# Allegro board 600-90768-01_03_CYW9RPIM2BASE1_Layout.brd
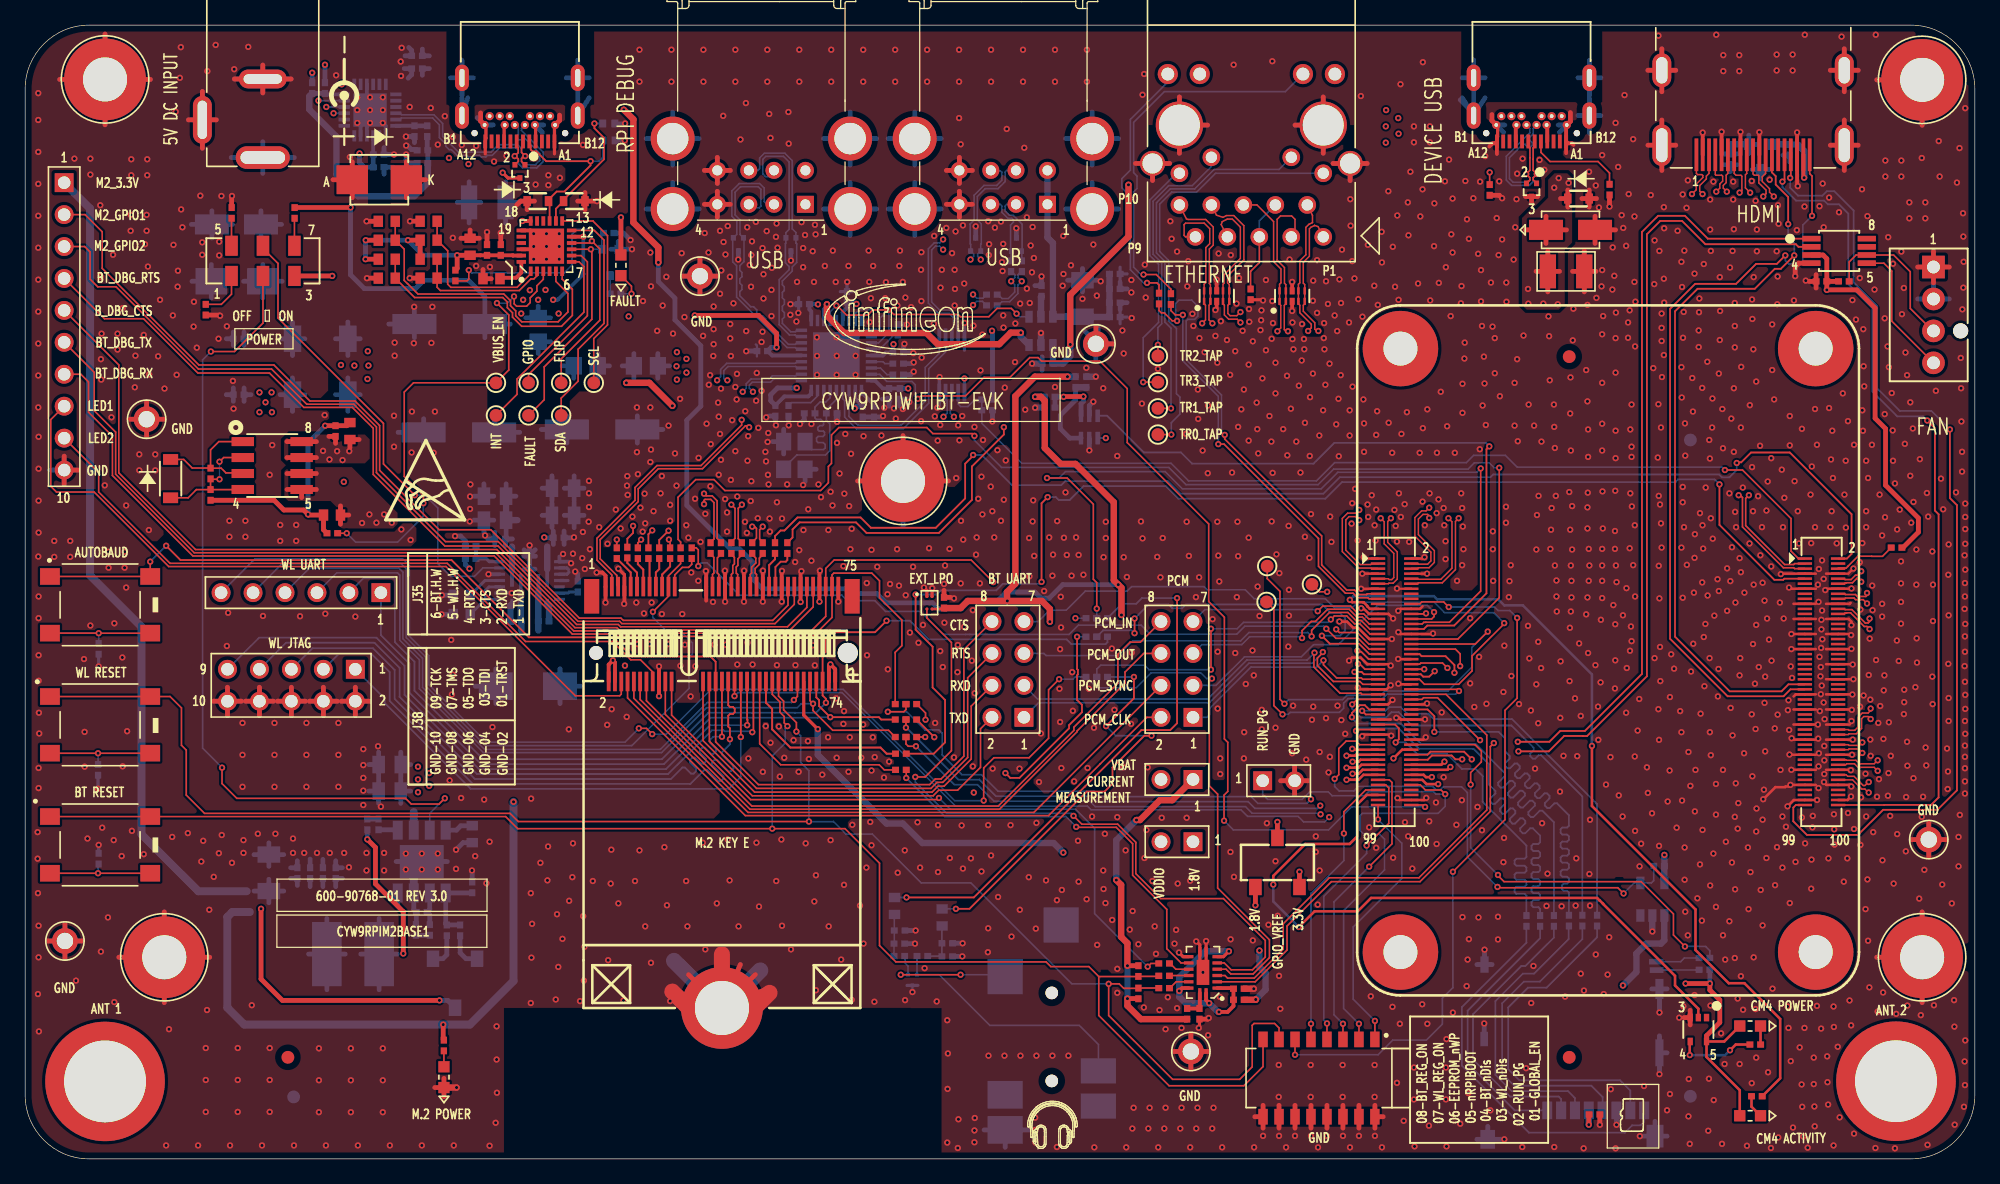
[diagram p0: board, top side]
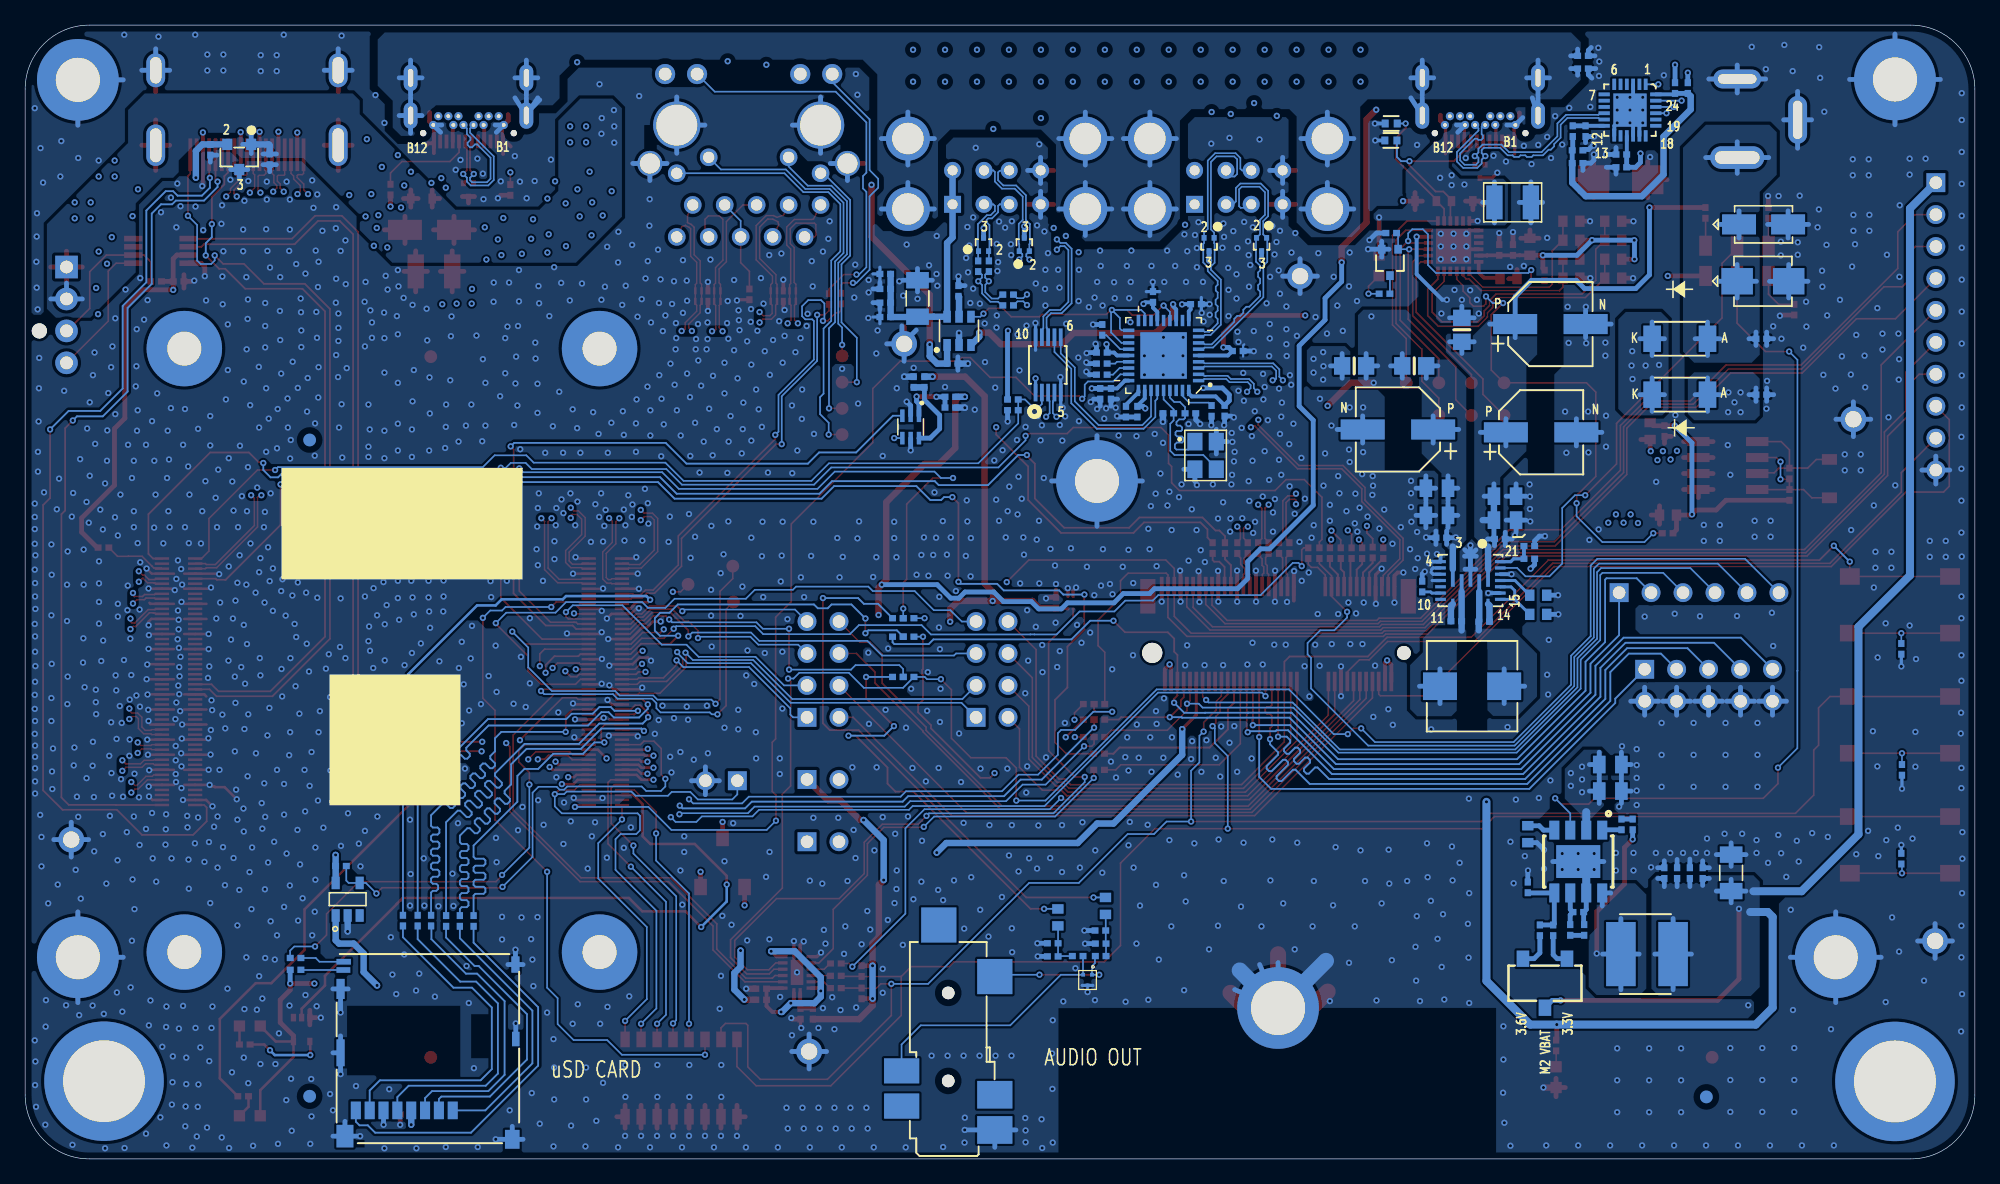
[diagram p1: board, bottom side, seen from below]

Outline 154.94 x 90.17 mm; copper layers: TOP, L02_GND, L03_PWR, L04, L05, BOTTOM. Coordinates in mm from the lower left corner of the outline.
Outline path: 0,85.09 0,5.08 arc(1.49,1.49) 5.08,0 149.86,0 arc(153.45,1.49) 154.94,5.08 154.94,85.09 arc(153.45,88.68) 149.86,90.17 5.08,90.17 arc(1.49,88.68) 0,85.09

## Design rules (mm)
constraint set DEFAULT: min track width 0.127
net group DIFFPAIR0: nets BT_USB_DN BT_USB_DP
net group DP3: nets USBRPI_DM USBRPI_DP
net group HD1: nets HD1_N HD1_P
net group HD1_M2: nets HD1_M2_N HD1_M2_P
net group HD1_PORT: nets HD1_PORT_N HD1_PORT_P
net group HD2: nets HD2_N HD2_P
net group HD3: nets HD3_N HD3_P
net group HD4: nets HD4_N HD4_P
net group PCIE_CLK_N: nets N17494909 PCIE_CLK_N
net group PCIE_CLK_P: nets N17494904 PCIE_CLK_P
net group PCIE_RX_N: nets N17494929 PCIE_RX_N
net group PCIE_RX_P: nets N17494926 PCIE_RX_P
net group PCIE_TX_N: nets N17494923 PCIE_TX_N
net group PCIE_TX_P: nets N17494920 PCIE_TX_P
net group SD_CLK: nets N17568415 SD_CLK
net group SD_CMD: nets N17568375 SD_CMD
net group SD_DAT0: nets N17569067 SD_DAT0
net group SD_DAT1: nets N17569095 SD_DAT1
net group SD_DAT2: nets N17568318 SD_DAT2
net group SD_DAT3: nets N17568347 SD_DAT3
net group TRD0: nets TRD0_N TRD0_P
net group TRD1: nets TRD1_N TRD1_P
net group TRD2: nets TRD2_N TRD2_P
net group TRD3: nets TRD3_N TRD3_P
net group USB2: nets USB2_N USB2_P
net group HDMI: nets HDMI0_CK_N HDMI0_CK_P HDMI0_D0_N HDMI0_D0_P HDMI0_D1_N HDMI0_D1_P HDMI0_D2_N HDMI0_D2_P
net group JTAG: nets WL_JTAG_TCK WL_JTAG_TDI WL_JTAG_TDO WL_JTAG_TMS
net group PWR: nets 1.8V 3.3V HDMI_5V M2_3.3V V3P3 VBUS VCCD VCCD_17758174 VDDD VDDIO
net group PWR_PH: nets 5V_IN GND_EARTH GPIO_VREF SD_PWR
net group SE_50E: nets GPIO8 GPIO9 HDMI0_SCL HDMI0_SDA PWM0_0 PWM0_1 PWR1 RXD SCL0 SDA0 TXD WL_JTAG_TRST WL_UART_RXD WL_UART_TXD
nets with their own width: min track width 0.381; nets GND

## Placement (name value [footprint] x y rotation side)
C1  10uF  [CAPC1005_IS0402Q]  81.24 63.25 180 bottom
C2  100uF  [CAPC3216_IS1206N]  84.03 68.43 90 bottom
C3  10uF  [CAPC1005_IS0402Q]  86.59 70.38 0 bottom
C4  10uF  [CAPC1005_IS0402Q]  86.59 69.19 0 bottom
C5  10uF  [CAPC1005_IS0402Q]  86.59 68.1 0 bottom
C6  10uF  [CAPC1005_IS0402Q]  86.59 66.95 0 bottom
C7  27pF  [CAPC1005_IS0402Q]  62.34 59.3 180 bottom
C8  27pF  [CAPC1005_IS0402Q]  64.1 59.3 0 bottom
C9  10uF  [CAPC1005_IS0402Q]  69.51 60.85 270 bottom
C10  10uF  [CAPC1005_IS0402Q]  68.65 60.85 270 bottom
C11  0.1uF  [CAPC1005_IS0402Q]  61.9 67.98 180 bottom
C12  0.1uF  [CAPC1005_IS0402Q]  65.31 68.55 90 bottom
C13  0.1uF  [CAPC1005_IS0402Q]  69.38 64.13 0 bottom
C14  0.1uF  [CAPC1005_IS0402Q]  66.55 59.43 270 bottom
C15  0.1uF  [CAPC1005_IS0402Q]  58.58 64.25 180 bottom
C16  0.1uF  [CAPC1005_IS0402Q]  59.62 59.5 270 bottom
C17  0.1uF  [CAPC1005_IS0402Q]  135.51 79.5 270 bottom
C18  0.1uF  [CAPC1005_IS0402Q]  140.22 80.26 270 bottom
C19  0.1uF  [CAPC1005_IS0402Q]  142.75 69.79 180 top
C20  10uF  [CAPC1005_IS0402Q]  124.71 3.53 0 top
C21  0.1uF  [CAPC1005_IS0402Q]  96.45 13.53 180 top
C22  0.1uF  [CAPC1005_IS0402Q]  93.32 11.54 270 top
C23  2.2uF  [CAPC1005_IS0402Q]  73.02 44.23 90 top
C27  0.1uF  [CAPC1005_IS0402Q]  28.08 26.6 90 bottom
C28  10uF  [CAPC2012_IS0805Q]  28.97 29.25 180 bottom
C29  10uF  [CAPC2012_IS0805Q]  28.97 31.36 180 bottom
C30  10uF  [CAPC1005_IS0402Q]  24.68 22.73 90 bottom
C31  10uF  [CAPC1005_IS0402Q]  23.66 22.73 90 bottom
C32  10uF  [CAPC1005_IS0402Q]  22.65 22.73 90 bottom
C33  10uF  [CAPC1005_IS0402Q]  21.63 22.73 90 bottom
C34  100uF  [CAPC3216_IS1206N]  19.37 22.75 90 bottom
C35  0.1uF  [CAPC1608_IS0603Q]  35.53 25.82 270 bottom
C36  1500pF  [CAPC1005_IS0402Q]  31.05 18.2 90 bottom
C41  3.3uF  [CAPC3225_1210N_H190]  122.45 70.59 180 top
C51  0.1uF  [CAPC1005_IS0402Q]  84.33 61.79 90 bottom
C52  0.1uF  [CAPC1005_IS0402Q]  81.42 59.76 0 bottom
C53  0.1uF  [CAPC1005_IS0402Q]  97.38 68.76 270 top
C55  0.1uF  [CAPC1005_IS0402Q]  73.28 17.14 0 bottom
C56  0.1uF  [CAPC1005_IS0402Q]  69.49 18.16 0 bottom
C57  10uF  [CAPC1005_IS0402Q]  71.3 16.13 180 bottom
C58  10uF  [CAPC1005_IS0402Q]  69.47 16.13 0 bottom
C59  0.1uF  [CAPC1005_IS0402Q]  28.09 79.88 0 bottom
C60  4.7uF  [CAPC1005_IS0402Q]  28.09 78.87 0 bottom
C61  1uF  [CAPC1005_IS0402Q]  30.94 81.74 270 bottom
C62  0.1uF  [CAPC1005_IS0402Q]  31.57 80.21 180 bottom
C63  4.7uF  [CAPC1005_IS0402Q]  31.57 79.2 180 bottom
C139  1uF  [CAPC1608_IS0603Q]  24.38 51.21 180 top
C144  1uF  [CAPC1608_IS0603Q]  25.81 57.89 90 top
C158  390pF  [CAPC1005_0402N]  46.41 81 0 bottom
C159  390pF  [CAPC1005_0402N]  46.38 82.35 0 bottom
C162  1uF  [CAPC1608_IS0603Q]  35.36 72.54 90 top
C165  0.1uF  [CAPC1005_IS0402Q]  37.8 72.29 90 top
C172  3.3uF  [CAPC3225_1210N_H190]  36.73 76.07 0 bottom
C173  0.1uF  [CAPC1005_IS0402Q]  36.7 72.29 90 top
C175  1uF  [CAPC1608_IS0603Q]  37.06 70 180 top
C180  0.01uF  [CAPC1005_IS0402Q]  31.14 87.73 0 bottom
C185  120uF  [CAPAE650X600N]  45.85 58.01 0 bottom
C191  10uF  [CAPC2012_IS0805Q]  42.75 51.18 0 bottom
C192  22uF  [CAPC2012_IS0805Q]  42.75 53.34 0 bottom
C195  0.1uF  [CAPC1005_IS0402Q]  42.4 49.4 0 bottom
C197  0.22uF  [CAPC1005_IS0402Q]  41.21 42.76 180 bottom
C210  0.22uF  [CAPC1005_IS0402Q]  39 42.72 0 bottom
C214  0.1uF  [CAPC1005_IS0402Q]  37.74 49.3 180 bottom
C215  10uF  [CAPC2012_IS0805Q]  37.34 50.8 180 bottom
C216  22uF  [CAPC2012_IS0805Q]  37.34 52.7 180 bottom
C224  1uF  [CAPC1608_IS0603Q]  34.7 43.31 0 bottom
C225  1uF  [CAPC1608_IS0603Q]  34.7 44.83 0 bottom
C227  68uF  [CAPAE650X600N]  34.47 57.78 180 bottom
C228  68uF  [CAPAE650X600N]  33.73 66.4 180 bottom
C229  33pF  [CAPC1005_IS0402Q]  31.51 19.63 180 bottom
D13  GREEN  [LEDC1608Q]  137.08 3.43 270 top
D14  RED  [LEDC1608Q]  137.08 10.57 270 top
D15  ORANGE  [LEDC1608Q]  33.28 6.5 180 top
D18  ESD5V0D5  [SODFL1608X77N]  40.74 76.17 0 top
D21  SMBJ24CA-E3/52  [DIOM5336X265N]  28.14 77.88 180 top
D24  ESD5V0D5  [SODFL1608X77N]  43.64 76.17 180 top
D25  NZH10C  [SODFL3516X120N]  11.56 54.1 270 top
D26  RED  [LEDC1608Q]  47.35 71.07 180 top
D27  PMEG3050BE  [SODFL4725X110N]  23.44 65.23 180 bottom
D28  PMEG3050BE  [SODFL4725X110N]  23.44 60.78 180 bottom
D29  ESD5V0D5  [SODFL1608X77N]  123.44 76.38 180 top
D30  SMAZ5V1-13-F  [DIOM4326_SMA_DO214ACN]  16.79 74.32 180 bottom
D31  SMBJ5V0A  [DIOM4336_SMB_DO214AAN]  16.84 69.8 180 bottom
D32  SMAZ5V1-13-F  [DIOM4326_SMA_DO214ACN]  122.81 73.89 0 top
J1  DX07S024XJ1R1100  [JAE_DX07S024XJ1]  122.46 80.92 180 top
J3  690-008-221P904  [USB-8P-690-008-221-904]  77.74 78.63 180 top
J4  690-008-221P904  [USB-8P-690-008-221-904]  58.51 78.63 180 top
J5  DF40C-100DS-0.4V(51)  [CON2X50_0P4_DF40C-100DS]  142.75 37.94 270 top
J8  690-019-298-412  [CON1X19_0P5_690-019-298-412]  137.31 79.86 180 top
J9  47053-1000  [MOLEX_47053-1000]  151.65 70.93 90 top
J10  DF40C-100DS-0.4V(51)  [CON2X50_0P4_DF40C-100DS]  108.83 37.94 270 top
J11  A70-112-331N126  [RJ45-A70-112-331N126]  96.94 80.72 0 top
J17  2201778-1  [CONMSD_2201778-1]  124.81 4.55 180 bottom
J21  PBC02SAAN  [CTST254PSS2]  92.81 30.18 180 top
J23  8038402-67G00E5T  [M_2_2230-XX-E_MDT420E02001]  55.37 40.24 0 top
J25  PBC04DAAN  [CTST254PDS8]  92.81 35.12 90 top
J30  PBC04DAAN  [CTST254PDS8]  79.37 35.12 90 top
J35  PBC06SAAN  [CTST254PSS6]  28.27 45.03 180 top
J36  PBC02SAAN  [CTST254PSS2]  92.81 25.22 180 top
J37  PBC10SAAN  [CTST254PSS10]  3.1 77.64 270 top
J38  PBC05DAAN  [CTST254PDS10]  26.24 38.94 180 top
J46  SJ-43515RS-SMT  [JACK-EARPHONE-ACI]  81.58 6.2 90 bottom
J47  DX07S024XJ1R1100  [JAE_DX07S024XJ1]  42.06 80.92 180 top
J48  RAPC722X  [SWCFT_RAPC722]  18.88 79.64 180 top
J49  PBC02SAAN  [CTST254PSS2]  98.34 30.07 0 top
L1  3.3uH  [INDS2_4P7MM_6X6]  26.05 16.29 270 bottom
L5  4.7uH  [IND_744311470]  39.95 37.59 0 bottom
M1  S001-00001-A42-R  [MT_PTH4_20]  55.37 12 180 top
MTH1  MTH  [MTGHOLE_TC650D350P]  150.75 16.03 180 top
MTH2  MTH  [MTGHOLE_TC650D350P]  6.35 85.85 180 top
MTH3  MTH  [MTGHOLE_TC650D350P]  150.75 85.82 180 top
MTH4  MTH  [MTGHOLE_TC650D350P]  11.05 16.03 180 top
MTH5  MTH  [MTGHOLE_TC650D350P]  69.76 53.92 180 top
NOREF  -  []  40.09 46 0 top
NOREF#2  -  []  21.44 63.88 90 top
NOREF#3  -  []  42.79 76.17 0 top
NOREF#4  -  [unnamed#2]  109.29 16.44 180 top
NOREF#5  -  []  37.54 43.95 90 top
NOREF#6  -  []  21.44 66.58 0 top
NOREF#7  -  [unnamed#3]  122.71 8.08 0 top
NOREF#8  -  [unnamed#3]  122.71 63.8 0 top
NOREF#9  -  []  -252.78 -168.83 0 top
NOREF#10  -  []  39.89 76.17 0 top
NOREF#11  -  []  40.09 76.6 0 top
NOREF#12  -  []  37.54 43.95 0 top
NOREF#13  -  []  25.99 77.88 0 top
NOREF#14  -  []  21.24 65.23 0 top
NOREF#15  -  []  122.59 76.38 0 top
NOREF#16  -  []  445.72 -90.09 0 top
NOREF#17  -  []  25.84 75.9 0 top
NOREF#18  -  []  25.84 75.9 90 top
NOREF#19  -  []  40.09 75.75 90 top
NOREF#20  -  [unnamed#2]  142.29 16.44 180 top
NOREF#21  -  []  205.85 235.41 0 top
NOREF#22  -  []  128.16 484.58 0 top
NOREF#23  -  []  124.61 42.96 0 top
NOREF#24  -  [unnamed#2]  6.35 6.16 180 top
NOREF#25  -  []  21.44 59.43 90 top
NOREF#26  -  []  16.99 -19.1 0 top
NOREF#27  -  [unnamed#2]  142.29 64.44 180 top
NOREF#28  -  []  153.57 1.61 0 top
NOREF#29  -  [unnamed#3]  20.88 8.08 0 top
NOREF#30  -  []  40.09 46.9 0 top
NOREF#31  -  []  166.32 97.87 0 top
NOREF#32  -  []  42.99 75.75 0 top
NOREF#33  -  []  24.64 -19.94 0 top
NOREF#34  -  []  42.46 47 90 top
NOREF#35  -  []  5.08 0 90 top
NOREF#36  -  [unnamed#2]  148.67 6.18 180 top
NOREF#37  -  []  21.44 62.13 0 top
NOREF#38  -  []  40.09 46 90 top
NOREF#39  -  []  21.24 60.78 0 top
NOREF#40  -  []  0 85.09 0 top
NOREF#41  -  []  122.79 75.95 0 top
NOREF#42  -  []  128.19 41.64 0 top
NOREF#43  -  [unnamed#2]  109.29 64.44 180 top
NOREF#44  -  []  44.29 75.75 90 top
NOREF#45  -  []  124.09 75.95 90 top
NOREF#46  -  []  445.72 -90.09 180 bottom
NOREF#47  -  [unnamed#3]  132.33 57.18 180 bottom
NOREF#48  -  [unnamed#3]  132.33 4.98 180 bottom
NOREF#49  -  [unnamed#3]  21.34 4.93 180 bottom
NOREF#50  -  []  126.06 69.39 180 bottom
NOREF#51  -  []  57.1 30.33 180 bottom
Q14  BSS138WH6327XTSA1  [SOT65P210X110-3N]  46.48 71.3 0 bottom
R1  2.2K  [RESC1005_IS0402Q]  76.45 60.4 180 bottom
R2  2.2K  [RESC1005_IS0402Q]  76.45 59.54 0 bottom
R3  12K OHM  [RESC1005_IS0402Q]  60.66 59.49 90 bottom
R4  6.49K  [RESC1005_IS0402Q]  80.77 69.03 90 bottom
R5  0 OHM  [RESC1005_IS0402Q]  79.2 71 270 bottom
R6  30K OHM  [RESC1005_IS0402Q]  69.38 63.25 0 bottom
R7  30K OHM  [RESC1005_IS0402Q]  69.34 65.93 90 bottom
R8  30K OHM  [RESC1005_IS0402Q]  67.46 59.43 270 bottom
R9  0 OHM  [RESC1005_IS0402Q]  78.35 71 90 bottom
R10  30K OHM  [RESC1005_IS0402Q]  69.38 62.37 0 bottom
R11  37.4K  [RESC1005_IS0402Q]  144.53 69.79 0 top
R12  330 OHM  [RESC1005_IS0402Q]  137.62 4.98 0 top
R13  470 OHM  [RESC1005_IS0402Q]  91.05 68.38 90 top
R14  470 OHM  [RESC1005_IS0402Q]  90.11 68.43 90 top
R15  0 OHM  [RESC1005_IS0402Q]  120.4 18.92 270 bottom
R16  0 OHM  [RESC1005_IS0402Q]  121.49 18.92 270 bottom
R17  0 OHM  [RESC1005_IS0402Q]  122.68 18.95 270 bottom
R18  0 OHM  [RESC1005_IS0402Q]  123.75 18.95 270 bottom
R19  0 OHM  [RESC1005_IS0402Q]  124.92 18.95 270 bottom
R20  0 OHM  [RESC1005_IS0402Q]  119.31 18.92 270 bottom
R21  390 OHM  [RESC1005_IS0402Q]  137.49 9.09 180 top
R22  0 OHM  [RESC1005_IS0402Q]  133.45 15.04 180 bottom
R23  0 OHM  [RESC1005_IS0402Q]  133.45 15.98 180 bottom
R24  12K OHM  [RESC1005_IS0402Q]  129.84 23.29 180 bottom
R25  10KOHM  [RESC1005_IS0402Q]  88.47 14.94 270 top
R26  0 OHM  [RESC1005_IS0402Q]  96.45 12.65 0 top
R27  0 OHM  [RESC1005_IS0402Q]  92.34 11.54 270 top
R28  0 OHM  [RESC1005_IS0402Q]  47.02 48.17 90 top
R29  0 OHM  [RESC1005_IS0402Q]  47.85 48.22 90 top
R30  0 OHM  [RESC1005_IS0402Q]  48.69 48.17 90 top
R31  2.2K  [RESC1005_IS0402Q]  90.51 13.58 180 top
R32  0 OHM  [RESC1005_IS0402Q]  49.53 48.17 90 top
R33  2.2K  [RESC1005_IS0402Q]  90.51 14.56 180 top
R34  0 OHM  [RESC1005_IS0402Q]  90.51 15.54 180 top
R35  0 OHM  [RESC1005_IS0402Q]  50.39 48.17 90 top
R36  0 OHM  [RESC1005_IS0402Q]  51.25 48.17 90 top
R37  0 OHM  [RESC1005_IS0402Q]  52.09 48.17 90 top
R38  10KOHM  [RESC1005_IS0402Q]  88.47 13.16 90 top
R39  0 OHM  [RESC1005_IS0402Q]  52.97 48.17 90 top
R40  0 OHM  [RESC1005_IS0402Q]  54.47 48.58 90 top
R41  0 OHM  [RESC1005_IS0402Q]  55.29 48.58 90 top
R42  0 OHM  [RESC1005_IS0402Q]  56.12 48.58 90 top
R43  0 OHM  [RESC1005_IS0402Q]  56.95 48.58 90 top
R44  0 OHM  [RESC1005_IS0402Q]  5.84 23.88 270 bottom
R45  0 OHM  [RESC1005_IS0402Q]  5.79 30.94 90 bottom
R46  0 OHM  [RESC1005_IS0402Q]  57.78 48.58 90 top
R47  0 OHM  [RESC1005_IS0402Q]  58.61 48.58 90 top
R48  0 OHM  [RESC1005_IS0402Q]  69.59 30.94 180 top
R49  0 OHM  [RESC1005_IS0402Q]  69.59 32.22 180 top
R50  0 OHM  [RESC1005_IS0402Q]  59.59 48.58 90 top
R51  0 OHM  [RESC1005_IS0402Q]  60.57 48.58 90 top
R52  0 OHM  [RESC1005_IS0402Q]  5.84 40.56 90 bottom
R53  0 OHM  [RESC1005_IS0402Q]  69.57 36.17 0 top
R54  0 OHM  [RESC1005_IS0402Q]  69.57 33.55 180 top
R55  0 OHM  [RESC1005_IS0402Q]  69.57 34.94 180 top
R57  0 OHM  [RESC1005_IS0402Q]  85.58 41.53 0 bottom
R58  750 OHM  [RESC1005_IS0402Q]  33.27 9.02 270 top
R60  10 OHM  [RESC1005_IS0402Q]  27.19 26.6 270 bottom
R61  47K  [RESC1005_IS0402Q]  33.51 18.18 90 bottom
R62  52.3K  [RESC1005_IS0402Q]  34.57 18.18 90 bottom
R63  12K OHM  [RESC1005_IS0402Q]  32.16 18.2 270 bottom
R64  15K  [RESC1005_IS0402Q]  35.53 21.59 90 bottom
R65  5.1K  [RESC1005_IS0402Q]  116.38 77.06 90 top
R69  0 OHM  [RESC1005_IS0402Q]  81.42 60.61 180 bottom
R70  0 OHM  [RESC1005_IS0402Q]  83.48 61.79 90 bottom
R80  0 OHM  [RESC1005_IS0402Q]  22.81 85.17 90 bottom
R82  82  [RESC1608_IS0603Q]  72.87 19.2 270 bottom
R83  82  [RESC1608_IS0603Q]  69.09 20.12 270 bottom
R84  124  [RESC1005_IS0402Q]  69.47 17.12 0 bottom
R85  124  [RESC1005_IS0402Q]  73.28 16.1 0 bottom
R86  0 OHM  [RESC1005_IS0402Q]  84.73 38.33 180 bottom
R87  0 OHM  [RESC1005_IS0402Q]  85.58 38.33 0 bottom
R88  0 OHM  [RESC1005_IS0402Q]  84.73 43 0 bottom
R89  0 OHM  [RESC1005_IS0402Q]  85.58 43 180 bottom
R92  0 OHM  [RESC1005_IS0402Q]  76.82 67.88 0 bottom
R93  0 OHM  [RESC1005_IS0402Q]  76.82 68.74 0 bottom
R94  0 OHM  [RESC1005_IS0402Q]  31.95 81.74 270 bottom
R95  0 OHM  [RESC1005_IS0402Q]  84.73 41.53 180 bottom
R96  0 OHM  [RESC1005_IS0402Q]  70.42 34.94 0 top
R97  0 OHM  [RESC1005_IS0402Q]  70.42 36.17 0 top
R98  0 OHM  [RESC1005_IS0402Q]  70.42 33.55 0 top
R297  1K  [RESC1005_IS0402Q]  24.41 49.76 0 top
R298  49.9K  [RESC1005_IS0402Q]  14.73 54.51 270 top
R302  10KOHM  [RESC1005_IS0402Q]  24.66 57.89 90 top
R321  0 OHM  [RESC1005_IS0402Q]  14.73 52.81 90 top
R347  2.2K  [RESC1005_IS0402Q]  34.19 70.26 270 top
R359  4.99K  [RESC1608_IS0603Q]  28.74 71.55 0 top
R360  0  [RESC1608_IS0603Q]  28.74 70.05 0 top
R364  0  [RESC1608_IS0603Q]  32.06 74.57 0 top
R365  4.99K  [RESC1608_IS0603Q]  32.06 73.07 0 top
R366  4.99K  [RESC1608_IS0603Q]  32.06 70.05 0 top
R367  0  [RESC1608_IS0603Q]  32.06 71.56 0 top
R368  4.99K  [RESC1608_IS0603Q]  28.74 74.57 0 top
R369  4.99K  [RESC1608_IS0603Q]  28.74 73.06 0 top
R372  100K  [RESC1005_IS0402Q]  31.14 86.72 0 bottom
R373  390  [RESC1005_IS0402Q]  46.91 68.81 0 bottom
R374  100K  [RESC1005_IS0402Q]  46.38 73.63 180 bottom
R383  0 OHM  [RESC2012_IS0805Q]  44.55 63.07 0 bottom
R384  0 OHM  [RESC1005_IS0402Q]  43.92 45.52 270 bottom
R390  0 OHM  [RESC2012_IS0805Q]  40.77 65.94 270 bottom
R393  47K  [RESC1005_IS0402Q]  16.97 60.78 0 bottom
R394  47K  [RESC1005_IS0402Q]  16.97 65.23 0 bottom
R398  100K  [RESC1005_IS0402Q]  21.41 75.23 270 top
R399  100K  [RESC1005_IS0402Q]  35.41 47.73 0 bottom
R400  100K  [RESC1005_IS0402Q]  16.41 75.23 270 top
R403  8.25K  [RESC1005_IS0402Q]  35.41 48.74 180 bottom
R404  5.1K  [RESC1005_IS0402Q]  125.91 77.09 90 top
R405  0 OHM  [RESC2012_IS0805Q]  49.33 63.07 0 bottom
R406  2.2K  [RESC1005_IS0402Q]  148.72 48.62 180 top
R407  0 OHM  [RESC1005_IS0402Q]  23.83 85.17 90 bottom
R408  100K  [RESC1005_IS0402Q]  14.35 67.54 270 top
SW2  PTS645-S-M-43-SMTR92-LFS  [SWPBS4_PTS645_SMT]  5.95 24.97 180 top
SW3  PTS645-S-M-43-SMTR92-LFS  [SWPBS4_PTS645_SMT]  5.95 34.52 180 top
SW4  PTS645-S-M-43-SMTR92-LFS  [SWPBS4_PTS645_SMT]  5.95 44.07 180 top
SW5  CJS-1200TB  [SWDPS2_CJS]  34.16 13.97 0 bottom
SW8  A6H-8101  [SWDPS16_OMRON_A6H-8101]  102.82 6.43 270 top
SW9  CJS-1200TB  [SWDPS2_CJS]  99.52 23.57 0 top
SW10  JS202011JCQN  [SW_JS202011JCQN]  18.9 71.42 0 top
TP1  PCB TP  [TP102C]  98.7 47.14 180 top
TP2  PCB TP  [TP102C]  102.26 45.69 180 top
TP4  BLACK  [TPT1_KOB_151-10X-RC]  9.65 58.83 270 top
TP5  BLACK  [TPT1_KOB_151-10X-RC]  53.63 70.21 270 top
TP6  BLACK  [TPT1_KOB_151-10X-RC]  3.16 17.33 180 top
TP7  BLACK  [TPT1_KOB_151-10X-RC]  92.64 8.54 180 top
TP8  BLACK  [TPT1_KOB_151-10X-RC]  85.09 64.82 180 top
TP9  BLACK  [TPT1_KOB_151-10X-RC]  151.28 25.39 180 top
TP10  PCB TP  [TP102C]  90.02 59.69 0 top
TP11  PCB TP  [TP102C]  90.02 63.86 0 top
TP12  PCB TP  [TP102C]  90.02 57.61 0 top
TP13  PCB TP  [TP102C]  90.02 61.77 0 top
TP31  PCB TP  [TP102C]  40.01 59.13 0 top
TP32  PCB TP  [TP102C]  37.41 61.72 0 top
TP33  PCB TP  [TP102C]  37.41 59.13 0 top
TP34  PCB TP  [TP102C]  40.01 61.72 0 top
TP35  PCB TP  [TP102C]  42.6 61.72 0 top
TP36  PCB TP  [TP102C]  45.19 61.72 0 top
TP37  PCB TP  [TP102C]  42.6 59.13 0 top
TP38  PCB TP  [TP102C]  98.65 44.3 0 top
U1  FSUSB42MUX  [MSOP50P490X300-10N]  73.67 63.15 90 bottom
U2  NCP380HSNAJAAT1G  [TSOP095P275_6_300]  80.73 65.85 90 bottom
U3  EMC2301-1-ACZL-TR  [MSOP65P490X110-8M]  144.15 72.21 0 top
U4  RT9742SNGV  [SOT23_1_2_3]  137.93 79.69 0 bottom
U6  TPD4EUSB30  [USON10_P100X250_050MM]  94.69 69.04 0 top
U7  TPD4EUSB30  [USON10_P100X250_050MM]  100.69 69.04 0 top
U8  74LVC1G07SE  [SOT65P210X215-6M]  132.97 10.29 180 top
U9  RT9742GGJ5  [TSOT23-5_1_2_3_4_5]  129.31 20.65 90 bottom
U10  74AVC4TD245BQ  [QFN50P350X250_16_HS200X100]  93.6 14.83 90 top
U11  32.768KHz  [XTALS4_1P0X0P41_1M55X0M85]  71.87 44.23 0 top
U12  AP64501SP-13  [SO8_P127_490X600]  31.52 23.65 270 bottom
U14  USB2514B  [QFN50P600X600_36_HS370]  64.47 63.9 0 bottom
U15  74LVCH1T45GW  [SC70-6_SC88-6_1_2_3_4_5_6]  84.57 58.21 270 bottom
U16  CY7C65223-24LTXIT  [QFN50P400X400X55_24_HS265N]  27.41 83.41 270 bottom
U18  TPD2EUSB30ADRTR  [SOT3_TPD2EUSB30ADRT]  70.51 14.17 0 bottom
U29  CYPD3177-24LQXQ  [QFN50P400X400_24_H280N]  41.43 72.59 90 top
U30  ESD5V3U2U-03F  [SOTFL40P120X59-3N]  39.32 78.54 270 top
U33  MP4245GVE-0001-Z  [QFN50P400X500X100-21N_NOFID]  40.09 46 270 bottom
U34  ESD5V3U2U-03F  [SOTFL40P120X59-3N]  119.71 77.06 270 top
U35  IRF9358TRPBF  [SOIC127P600X175-8N]  19.63 55.14 0 top
U36  ESD5V3U2U-03F  [SOTFL40P120X59-3N]  78.78 72.72 90 bottom
U37  ESD5V3U2U-03F  [SOTFL40P120X59-3N]  75.54 72.72 90 bottom
U38  ESD5V3U2U-03F  [SOTFL40P120X59-3N]  56.68 72.73 270 bottom
U39  ESD5V3U2U-03F  [SOTFL40P120X59-3N]  60.85 72.73 270 bottom
Y1  24.000MHz  [XTALS4_3M2X2M5]  61.13 55.95 180 bottom

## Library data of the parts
C1-C23 C27-C36 C41 C51-C53 C55-C63 C139 C144 C162 C165 C172 C173 C175 C180 C191 C192 C195 C197 C210 C214-C216 C224 C225 C229 = CAP: User Part Number: Part No
C158 C159 = CAP
C185 C227 C228 = CAP-PN
D13-D15 D26 = DIO-LED: User Part Number: Part No
D18 D24 D29 = DIO-TVS-ESD
D21 = DIO-TVS-BIPOLAR
D25 = DIO-ZENER
D27 D28 = DIO-SCHOTTKY
D30 D32 = DIO-ZENER: User Part Number: Part No
D31 = DIO-TVS: User Part Number: Part No
J1 J47 = CONN_USB_TYPEC-24P-4SH
J3 J4 = USB_TYPEA_2DECK_4SH_J: User Part Number: Part No
J5 J10 = SKT_100_ODD_EVEN_J
J8 = CONN_HDMI_TYPE-A_19P
J9 = HDR1X4-LOCK-1R-J: User Part Number: Part No
J11 = CONN_RJ45_10P_2LED
J17 = CONN_uSD_2201778-1
J21 J36 J49 = HDR1X2-J: User Part Number: Part No
J23 = SKT_M_2_3030-xx-E_MDT420E02001
J25 J30 = HDR2X4R-J: User Part Number: Part No
J35 = HDR1X6-J: User Part Number: Part No
J37 = HDR1X10-J: User Part Number: Part No
J38 = HDR2X5R-J: User Part Number: PART NUMBER; Tolerance: TOLERANCE
J46 = CON-SJ-43515RS-SMT-J
J48 = CON-CNTR-SLEV-SHNT-J: User Part Number: Part No
L1 = IND-SHIELDED-NO-DOT: User Part Number: Part No
L5 = IND
M1 = SM3ZS067U410-NUT1-R1200
MTH1-MTH5 = MTH: User Part Number: Part No
NOREF#4 NOREF#20 NOREF#24 NOREF#27 NOREF#36 NOREF#43 = -: User Part Number: Part No
Q14 = FET-MOS-N
R1-R14 R21-R39 R44 R45 R48-R55 R57 R58 R60-R65 R69 R70 R80 R82-R89 R92-R98 R297 R298 R302 R321 R347 R359 R360 R364-R369 R372-R374 R384 R393 R394 R398-R400 R403 R404 R406-R408 = RES: User Part Number: Part No
R15-R20 = RES: User Part Number: Part No; signal model: RES_RESC1005_IS0402Q_DISCRETE_0_0_OHM
R40-R43 R46 R47 = RES: User Part Number: Part No; signal model: DEFAULT_RESISTOR_0.001OHM_1_2
R383 R390 R405 = RES
SW2-SW4 = SW-SPST-12-34: User Part Number: Part No
SW5 SW9 = SW-DIP-1
SW8 = SW-DIP-8: User Part Number: Part No
SW10 = SW_DPDT_JS202011CQN
TP1 TP2 TP10-TP13 TP31-TP38 = TP
TP4-TP9 = TP: User Part Number: Part No
U1 = FSUSB42MUX_MSOP10
U2 = NCP380_TSOP-6: User Part Number: Part No
U3 = EMC2301_MSOP8
U4 = RT9742SNGV_SOT23_3
U6 U7 = TPD4EUSB30_USON10
U8 = BUF-1
U9 = RT9742GGJ5_TSOT23-5: User Part Number: Part No
U10 = 74AVC4TD245BQ: User Part Number: Part No
U11 = SiT1532: User Part Number: Part No
U12 = AP64501_SO-8EP
U14 = USB2514B_SQFN36: User Part Number: Part No
U15 = 74XX1T45-SO6: User Part Number: Part No
U16 = CY7C65223_QFN24
U18 = TPD2EUSB30
U29 = CYPD3177-24LQXQ_QFN24
U30 U34 U36-U39 = ESD5V3U2U-03F
U33 = MP4245_QFN21
U35 = MOSFET-P_DUAL_SO8
Y1 = XTAL-1G3G: User Part Number: Part No

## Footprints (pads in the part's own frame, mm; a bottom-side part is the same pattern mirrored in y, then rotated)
CAPAE650X600N
  rect 3.5x1.6 smd: N(2.8,0) P(-2.8,0)
CAPC1005_0402N
  rect 0.56x0.62 smd: 1(-0.48,0) 2(0.48,0)
CAPC1005_IS0402Q
  rect 0.55x0.5 smd: 1(-0.425,0) 2(0.425,0)
CAPC1608_IS0603Q
  rect 0.75x0.9 smd: 1(-0.675,0) 2(0.675,0)
CAPC2012_IS0805Q
  rect 1x1.4 smd: 1(-0.88,0) 2(0.88,0)
CAPC3216_IS1206N
  rect 1.3x1.8 smd: 1(-1.45,0) 2(1.45,0)
CAPC3225_1210N_H190
  rect 1.3x2.7 smd: 1(-1.45,0) 2(1.45,0)
CON1X19_0P5_690-019-298-412
  rect 0.3x2.6 smd: 1(4.5,0) 2(4,0) 3(3.5,0) 4(3,0) 5(2.5,0) 6(2,0) 7(1.5,0) 8(1,0) 9(0.5,0) 10(0,0) 11(-0.5,0) 12(-1,0) 13(-1.5,0) 14(-2,0) 15(-2.5,0) 16(-3,0) 17(-3.5,0) 18(-4,0) 19(-4.5,0)
  oval 1.5x3.3 hole 0.9x2.7: SH1(-7.25,-0.76) SH2(7.25,-0.76)
  oval 1.5x2.7 hole 0.9x2.1: SH3(-7.25,-6.72) SH4(7.25,-6.72)
CON2X50_0P4_DF40C-100DS
  rect 0.2x1.14 smd: 1(-9.8,-1.32) 2(-9.8,1.32) 3(-9.4,-1.32) 4(-9.4,1.32) 5(-9,-1.32) 6(-9,1.32) 7(-8.6,-1.32) 8(-8.6,1.32) 9(-8.2,-1.32) 10(-8.2,1.32) 11(-7.8,-1.32) 12(-7.8,1.32) 13(-7.4,-1.32) 14(-7.4,1.32) 15(-7,-1.32) 16(-7,1.32) 17(-6.6,-1.32) 18(-6.6,1.32) 19(-6.2,-1.32) 20(-6.2,1.32) 21(-5.8,-1.32) 22(-5.8,1.32) 23(-5.4,-1.32) 24(-5.4,1.32) 25(-5,-1.32) 26(-5,1.32) 27(-4.6,-1.32) 28(-4.6,1.32) 29(-4.2,-1.32) 30(-4.2,1.32) 31(-3.8,-1.32) 32(-3.8,1.32) 33(-3.4,-1.32) 34(-3.4,1.32) 35(-3,-1.32) 36(-3,1.32) 37(-2.6,-1.32) 38(-2.6,1.32) 39(-2.2,-1.32) 40(-2.2,1.32) 41(-1.8,-1.32) 42(-1.8,1.32) 43(-1.4,-1.32) 44(-1.4,1.32) 45(-1,-1.32) 46(-1,1.32) 47(-0.6,-1.32) 48(-0.6,1.32) 49(-0.2,-1.32) 50(-0.2,1.32) 51(0.2,-1.32) 52(0.2,1.32) 53(0.6,-1.32) 54(0.6,1.32) 55(1,-1.32) 56(1,1.32) 57(1.4,-1.32) 58(1.4,1.32) 59(1.8,-1.32) 60(1.8,1.32) 61(2.2,-1.32) 62(2.2,1.32) 63(2.6,-1.32) 64(2.6,1.32) 65(3,-1.32) 66(3,1.32) 67(3.4,-1.32) 68(3.4,1.32) 69(3.8,-1.32) 70(3.8,1.32) 71(4.2,-1.32) 72(4.2,1.32) 73(4.6,-1.32) 74(4.6,1.32) 75(5,-1.32) 76(5,1.32) 77(5.4,-1.32) 78(5.4,1.32) 79(5.8,-1.32) 80(5.8,1.32) 81(6.2,-1.32) 82(6.2,1.32) 83(6.6,-1.32) 84(6.6,1.32) 85(7,-1.32) 86(7,1.32) 87(7.4,-1.32) 88(7.4,1.32) 89(7.8,-1.32) 90(7.8,1.32) 91(8.2,-1.32) 92(8.2,1.32) 93(8.6,-1.32) 94(8.6,1.32) 95(9,-1.32) 96(9,1.32) 97(9.4,-1.32) 98(9.4,1.32) 99(9.8,-1.32) 100(9.8,1.32)
CONMSD_2201778-1
  rect 0.8x1.4 smd: 1(3.85,-0.7) 2(2.75,-0.7) 3(1.65,-0.7) 4(0.55,-0.7) 5(-0.55,-0.7) 6(-1.65,-0.7) 7(-2.75,-0.7) 8(-3.85,-0.7)
  rect 1.15x0.45 smd: 9(-4.815,11.125)
  rect 1.1x0.45 smd: 10(-4.84,10.465)
  rect 1.35x1.8 smd: 11(-4.715,-2.75)
  rect 0.65x2.14 smd: 12(-5.065,3.88)
  rect 0.65x1.6 smd: 13(-5.065,8.96)
  rect 0.65x1.3 smd: 14(8.835,10.9)
  rect 0.6x1.15 smd: 15(8.86,4.975)
  rect 1.16x1.5 smd: 16(8.58,-3)
CTST254PDS8
  rect 1.5x1.5 hole 1: 1(0,0)
  round 1.5 hole 1: 2(0,2.54) 3(2.54,0) 4(2.54,2.54) 5(5.08,0) 6(5.08,2.54) 7(7.62,0) 8(7.62,2.54)
CTST254PDS10
  rect 1.5x1.5 hole 1: 1(0,0)
  round 1.5 hole 1: 2(0,2.54) 3(2.54,0) 4(2.54,2.54) 5(5.08,0) 6(5.08,2.54) 7(7.62,0) 8(7.62,2.54) 9(10.16,0) 10(10.16,2.54)
CTST254PSS2
  rect 1.5x1.5 hole 1: 1(0,0)
  round 1.5 hole 1: 2(2.54,0)
CTST254PSS6
  rect 1.5x1.5 hole 1: 1(0,0)
  round 1.5 hole 1: 2(2.54,0) 3(5.08,0) 4(7.62,0) 5(10.16,0) 6(12.7,0)
CTST254PSS10
  rect 1.5x1.5 hole 1: 1(0,0)
  round 1.5 hole 1: 2(2.54,0) 3(5.08,0) 4(7.62,0) 5(10.16,0) 6(12.7,0) 7(15.24,0) 8(17.78,0) 9(20.32,0) 10(22.86,0)
DIOM4326_SMA_DO214ACN
  rect 2.7x1.6 smd: A(1.95,0) C(-1.95,0)
DIOM4336_SMB_DO214AAN
  rect 2.5x2.1 smd: A(2.05,0) C(-2.05,0)
DIOM5336X265N
  rect 2.5x2.3 smd: 1(-2.15,0) 2(2.15,0)
IND_744311470
  rect 2.7x2.2 smd: 1(-2.55,0) 2(2.55,0)
INDS2_4P7MM_6X6
  rect 5.1x2.35 smd: 1(0,-2.075) 2(0,2.075)
JACK-EARPHONE-ACI
  round 1.001 hole 1.699 unplated: (0,0) (7,0)
  rect 2.2x2.799 smd: 1(-3.899,-3.701) 4(-1.1,-3.701)
  rect 2.799x2.799 smd: 2(8.301,-3.701) 5(12.4,0.749)
  rect 1.999x2.799 smd: 3(0.8,3.701) 6(-1.999,3.701)
JAE_DX07S024XJ1
  round 0.5 hole 0.75 unplated: (-0.85,-0.66)
  round 0.5 hole 0.95x0.75 unplated: (6.35,-0.66)
  rect 0.3x1.1 smd: A1(0,0) A2(0.5,0) A3(1,0) A4(1.5,0) A5(2,0) A6(2.5,0) A7(3,0) A8(3.5,0) A9(4,0) A10(4.5,0) A11(5,0) A12(5.5,0)
  round 0.65 hole 0.305: B1(5.55,-1.31) B2(5.15,-2.01) B3(4.35,-2.01) B4(3.95,-1.31) B5(3.55,-2.01) B6(3.15,-1.31) B7(2.35,-1.31) B8(1.95,-2.01) B9(1.55,-1.31) B10(1.15,-2.01) B11(0.35,-2.01) B12(-0.05,-1.31)
  oval 1.1x2.1 hole 0.406x1.422: SH1(-1.85,-2.06) SH2(7.35,-2.06) SH3(-1.85,-5.06) SH4(7.35,-5.06)
LEDC1608Q
  rect 0.9x0.9 smd: A(0,-0.826) C(0,0.826)
M_2_2230-XX-E_MDT420E02001
  rect 1.2x2.75 smd: (-10.35,4.5) (10.35,4.5)
  round 1.1 hole 1.1 unplated: (-10,0)
  round 1.6 hole 1.6 unplated: (10,0)
  rect 0.3x1.55 smd: 1(-9.25,5.275) 2(-9,-2.275) 3(-8.75,5.275) 4(-8.5,-2.275) 5(-8.25,5.275) 6(-8,-2.275) 7(-7.75,5.275) 8(-7.5,-2.275) 9(-7.25,5.275) 10(-7,-2.275) 11(-6.75,5.275) 12(-6.5,-2.275) 13(-6.25,5.275) 14(-6,-2.275) 15(-5.75,5.275) 16(-5.5,-2.275) 17(-5.25,5.275) 18(-5,-2.275) 19(-4.75,5.275) 20(-4.5,-2.275) 21(-4.25,5.275) 22(-4,-2.275) 23(-3.75,5.275) 32(-1.5,-2.275) 33(-1.25,5.275) 34(-1,-2.275) 35(-0.75,5.275) 36(-0.5,-2.275) 37(-0.25,5.275) 38(0,-2.275) 39(0.25,5.275) 40(0.5,-2.275) 41(0.75,5.275) 42(1,-2.275) 43(1.25,5.275) 44(1.5,-2.275) 45(1.75,5.275) 46(2,-2.275) 47(2.25,5.275) 48(2.5,-2.275) 49(2.75,5.275) 50(3,-2.275) 51(3.25,5.275) 52(3.5,-2.275) 53(3.75,5.275) 54(4,-2.275) 55(4.25,5.275) 56(4.5,-2.275) 57(4.75,5.275) 58(5,-2.275) 59(5.25,5.275) 60(5.5,-2.275) 61(5.75,5.275) 62(6,-2.275) 63(6.25,5.275) 64(6.5,-2.275) 65(6.75,5.275) 66(7,-2.275) 67(7.25,5.275) 68(7.5,-2.275) 69(7.75,5.275) 70(8,-2.275) 71(8.25,5.275) 72(8.5,-2.275) 73(8.75,5.275) 74(9,-2.275) 75(9.25,5.275)
MOLEX_47053-1000
  round 1.2 hole 1.25 unplated: (-5.08,-2.16)
  rect 1.8x1.8 hole 1.02: 1(0,0)
  round 1.8 hole 1.02: 2(-2.54,0) 3(-5.08,0) 4(-7.62,0)
MSOP50P490X300-10N
  rect 1.4x0.3 smd: 1(-2.2,0.975) 2(-2.2,0.475) 3(-2.2,-0.025) 4(-2.2,-0.525) 5(-2.2,-1.025) 6(2.2,-1.025) 7(2.2,-0.525) 8(2.2,-0.025) 9(2.2,0.475) 10(2.2,0.975)
MSOP65P490X110-8M
  rect 1.45x0.45 smd: 1(-2.2,0.975) 2(-2.2,0.325) 3(-2.2,-0.325) 4(-2.2,-0.975) 5(2.2,-0.975) 6(2.2,-0.325) 7(2.2,0.325) 8(2.2,0.975)
MT_PTH4_20
  round 6.5 hole 4.3: 1(0,0)
MTGHOLE_TC650D350P
  round 6.5 hole 3.5: 1(0,0)
QFN50P350X250_16_HS200X100
  rect 0.76x0.26 smd: 1(-1.635,-0.25) 8(1.635,-0.25) 9(1.635,0.25) 16(-1.635,0.25)
  rect 0.26x0.76 smd: 2(-1.25,-1.135) 3(-0.75,-1.135) 4(-0.25,-1.135) 5(0.25,-1.135) 6(0.75,-1.135) 7(1.25,-1.135) 10(1.25,1.135) 11(0.75,1.135) 12(0.25,1.135) 13(-0.25,1.135) 14(-0.75,1.135) 15(-1.25,1.135)
  rect 2x1 smd: EP(0,0)
QFN50P400X400_24_H280N
  rect 0.75x0.3 smd: 1(-2,1.25) 2(-2,0.75) 3(-2,0.25) 4(-2,-0.25) 5(-2,-0.75) 6(-2,-1.25) 13(2,-1.25) 14(2,-0.75) 15(2,-0.25) 16(2,0.25) 17(2,0.75) 18(2,1.25)
  rect 0.3x0.75 smd: 7(-1.25,-2) 8(-0.75,-2) 9(-0.25,-2) 10(0.25,-2) 11(0.75,-2) 12(1.25,-2) 19(1.25,2) 20(0.75,2) 21(0.25,2) 22(-0.25,2) 23(-0.75,2) 24(-1.25,2)
  rect 2.8x2.8 smd: H(0,0)
QFN50P400X400X55_24_HS265N
  rect 0.9x0.3 smd: 1(-2.05,1.25) 2(-2.05,0.75) 3(-2.05,0.25) 4(-2.05,-0.25) 5(-2.05,-0.75) 6(-2.05,-1.25) 13(2.05,-1.25) 14(2.05,-0.75) 15(2.05,-0.25) 16(2.05,0.25) 17(2.05,0.75) 18(2.05,1.25)
  rect 0.3x0.9 smd: 7(-1.25,-2.05) 8(-0.75,-2.05) 9(-0.25,-2.05) 10(0.25,-2.05) 11(0.75,-2.05) 12(1.25,-2.05) 19(1.25,2.05) 20(0.75,2.05) 21(0.25,2.05) 22(-0.25,2.05) 23(-0.75,2.05) 24(-1.25,2.05)
  rect 2.65x2.65 smd: H(0,0)
QFN50P400X500X100-21N_NOFID
  rect 2.8x0.3 smd: 1(-0.9,1.4) 2(-0.9,0) 3(-0.9,-1.4) 12(0.9,-0.7) 13(0.9,0.7)
  rect 0.25x0.85 smd: 4(-1.5,-2.375) 5(-1,-2.375) 6(-0.5,-2.375) 7(0,-2.375) 8(0.5,-2.375) 9(1,-2.375) 10(1.5,-2.375) 15(1.5,2.375) 16(1,2.375) 17(0.5,2.375) 18(0,2.375) 19(-0.5,2.375) 20(-1,2.375) 21(-1.5,2.375)
  rect 0.85x0.25 smd: 11(1.875,-1.4) 14(1.875,1.4)
QFN50P600X600_36_HS370
  rect 0.9x0.28 smd: 1(-2.78,2) 2(-2.78,1.5) 3(-2.78,1) 4(-2.78,0.5) 5(-2.78,0) 6(-2.78,-0.5) 7(-2.78,-1) 8(-2.78,-1.5) 9(-2.78,-2) 19(2.78,-2) 20(2.78,-1.5) 21(2.78,-1) 22(2.78,-0.5) 23(2.78,0) 24(2.78,0.5) 25(2.78,1) 26(2.78,1.5) 27(2.78,2)
  rect 0.28x0.9 smd: 10(-2,-2.78) 11(-1.5,-2.78) 12(-1,-2.78) 13(-0.5,-2.78) 14(0,-2.78) 15(0.5,-2.78) 16(1,-2.78) 17(1.5,-2.78) 18(2,-2.78) 28(2,2.78) 29(1.5,2.78) 30(1,2.78) 31(0.5,2.78) 32(0,2.78) 33(-0.5,2.78) 34(-1,2.78) 35(-1.5,2.78) 36(-2,2.78)
  rect 3.7x3.7 smd: H(0,0)
RESC1005_IS0402Q
  rect 0.55x0.5 smd: 1(-0.425,0) 2(0.425,0)
RESC1608_IS0603Q
  rect 0.75x0.9 smd: 1(-0.675,0) 2(0.675,0)
RESC2012_IS0805Q
  rect 1.295x1.397 smd: 1(-0.953,0) 2(0.953,0)
RJ45-A70-112-331N126
  round 1.4 hole 0.9: P1(6.215,-7.39) P2(4.945,-4.85) P3(3.675,-7.39) P4(2.405,-4.85) P5(1.135,-7.39) P6(-0.135,-4.85) P7(-1.405,-7.39) P8(-2.675,-4.85) P9(-3.945,-7.39) P10(-5.215,-4.85) P11(6.215,-2.33) P12(3.675,-1.06) P13(-2.675,-1.06) P14(-5.215,-2.33)
  round 1.6 hole 1.02: P15(7.14,5.56) P16(4.6,5.56) P17(-3.6,5.56) P18(-6.14,5.56)
  round 2 hole 1.6: SH1(8.35,-1.55) SH2(-7.35,-1.55)
  round 3.759 hole 3.25: SH3(6.215,1.5) SH4(-5.215,1.5)
SC70-6_SC88-6_1_2_3_4_5_6
  rect 1x0.35 smd: 1(-0.889,0.66) 2(-0.889,0) 3(-0.889,-0.66) 4(0.889,-0.66) 5(0.889,0) 6(0.889,0.66)
SO8_P127_490X600
  rect 1.505x0.802 smd: 1(-2.498,1.905) 2(-2.498,0.635) 3(-2.498,-0.635) 4(-2.498,-1.905) 5(2.498,-1.905) 6(2.498,-0.635) 7(2.498,0.635) 8(2.498,1.905)
  rect 2.613x3.502 smd: 9(0,0)
SODFL1608X77N
  rect 0.6x0.8 smd: A(-0.85,0) K(0.85,0)
SODFL3516X120N
  rect 0.85x1.2 smd: A(1.525,0) C(-1.525,0)
SODFL4725X110N
  rect 1.4x2.1 smd: A(2.2,0) C(-2.2,0)
SOIC127P600X175-8N
  rect 1.78x0.72 smd: 1(-2.34,1.905) 2(-2.34,0.635) 3(-2.34,-0.635) 4(-2.34,-1.905) 5(2.34,-1.905) 6(2.34,-0.635) 7(2.34,0.635) 8(2.34,1.905)
SOT3_TPD2EUSB30ADRT
  rect 0.3x0.3 smd: 1(-0.35,-0.471) 2(0.35,-0.471) 3(0,0.379)
SOT23_1_2_3
  rect 0.8x0.9 smd: 1(-0.95,-1) 2(0.95,-1) 3(0,1)
SOT65P210X110-3N
  rect 0.6x0.7 smd: D(0,1.05) G(-0.65,-1.05) S(0.65,-1.05)
SOT65P210X215-6M
  rect 0.42x0.6 smd: 1(-0.65,-0.95) 2(0,-0.95) 3(0.65,-0.95) 4(0.65,0.95) 5(-0.65,0.95)
SOTFL40P120X59-3N
  rect 0.45x0.4 smd: 1(-0.525,0.4) 2(-0.525,-0.4) 3(0.525,0)
SW_JS202011JCQN
  rect 1x1.6 smd: 1(-2.5,-1.2) 2(0,-1.2) 3(2.5,-1.2) 5(-2.5,1.2) 6(0,1.2) 7(2.5,1.2)
SWCFT_RAPC722
  oval 4.3x1.8 hole 3.55x1: 1(0,0)
  oval 3.8x1.5 hole 3.05x0.75: 2(0,-6.248)
  oval 1.5x3.8 hole 0.75x3.05: 3(4.8,-3)
SWDPS2_CJS
  rect 1x1.3 smd: 1(-1.75,-1.95) 2(0,1.95) 3(1.75,-1.95)
SWDPS16_OMRON_A6H-8101
  rect 1.25x0.75 smd: 1(-3.075,4.445) 2(-3.075,3.175) 3(-3.075,1.905) 4(-3.075,0.635) 5(-3.075,-0.635) 6(-3.075,-1.905) 7(-3.075,-3.175) 8(-3.075,-4.445) 9(3.075,-4.445) 10(3.075,-3.175) 11(3.075,-1.905) 12(3.075,-0.635) 13(3.075,0.635) 14(3.075,1.905) 15(3.075,3.175) 16(3.075,4.445)
SWPBS4_PTS645_SMT
  rect 1.575x1.321 smd: 1(-3.984,2.254) 2(3.984,2.254) 3(-3.984,-2.254) 4(3.984,-2.254)
TP102C
  round 1.016 smd: 1(0,0)
TPT1_KOB_151-10X-RC
  round 2.05 hole 1.3: 1(0,0)
TSOP095P275_6_300
  rect 0.95x0.6 smd: 1(-1.125,0.95) 2(-1.125,0) 3(-1.125,-0.95) 4(1.125,-0.95) 5(1.125,0) 6(1.125,0.95)
TSOT23-5_1_2_3_4_5
  rect 1x0.65 smd: 1(-1.295,0.952) 2(-1.295,0) 3(-1.295,-0.952) 4(1.295,-0.952) 5(1.295,0.952)
unnamed#2
  round 6 hole 2.7: 1(0,0)
unnamed#3
  round 1.016 smd: (0,0)
USB-8P-690-008-221-904
  rect 1.35x1.35 hole 0.8: 1(-3.5,2.71)
  round 1.35 hole 0.8: 2(-1,2.71) 3(1,2.71) 4(3.5,2.71) 5(-3.5,0.01) 6(-1,0.01) 7(1,0.01) 8(3.5,0.01)
  round 3.5 hole 2.5: SH1(-7.05,3.08) SH2(7.05,3.08) SH3(-7.05,-2.52) SH4(7.05,-2.52)
USON10_P100X250_050MM
  rect 0.2x0.565 smd: 1(-1,-0.835) 2(-0.5,-0.835) 4(0.5,-0.835) 5(1,-0.835) 6(1,0) 7(0.5,0) 9(-0.5,0) 10(-1,0)
  rect 0.4x0.565 smd: 3(0,-0.835) 8(0,0)
XTALS4_1P0X0P41_1M55X0M85
  round 0.25 smd: 1(-0.205,0.5) 2(-0.205,-0.5) 3(0.205,-0.5) 4(0.205,0.5)
XTALS4_3M2X2M5
  rect 1.2x1.4 smd: 1(-0.85,1.1) 2(-0.85,-1.1) 3(0.85,-1.1) 4(0.85,1.1)

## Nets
1.8V: J10.88 J10.90 J36.1 R26.2 R69.2 R80.2 SW9.1
3.3V: C9.1 C10.1 C11.1 C12.1 C13.1 C14.1 C15.1 C16.1 C19.1 D13.A D14.A J10.84 J10.86 J11.P15 J11.P17 R11.1 R22.1 R24.1 R406.1 R407.2 SW9.3(B2) SW10.3 U1.1(VCC) U3.3(VDD) U8.5 U9.5 U14.5 U14.10 U14.15 U14.23 U14.27 U14.29 U14.36
3V3_EN: SW10.2 U12.3
5V_EN: SW10.6 U33.20
5V_IN: C214.1 C215.1 C216.1 C227.P C228.P R390.2 R398.1 U33.1(VIN)
GND: C1.2 C2.2 C3.2 C4.2 C5.2 C6.2 C7.2 C8.2 C9.2 C10.2 C11.2 C12.2 C13.2 C14.2 C15.2 C16.2 C17.2 C18.2 C19.2 C20.2 C21.1 C22.2 C23.2 C28.2 C29.2 C30.2 C31.2 C32.2 C33.2 C34.2 C35.2 C36.2 C41.1 C51.2 C52.1 C53.2 C55.2 C56.2 C59.2 C60.2 C61.2 C62.2 C63.2 C158.2 C159.2 C162.2 C165.2 C172.1 C173.2 C175.2 C180.1 C185.N C191.2 C192.2 C195.2 C214.2 C215.2 C216.2 C224.1 C225.1 C227.N C228.N C229.2 D15.C(CATHODE) D18.A D21.2 D24.A D29.A D30.A D31.A D32.A J1.A1 J1.A12 J1.B1 J1.B12 J3.4 J3.8 J4.4 J4.8 J5.7 J5.8 J5.13 J5.14 J5.19 J5.20 J5.25 J5.26 J5.31 J5.32 J5.37 J5.38 J5.44 J5.50 J5.55 J5.56 J5.61 J5.62 J5.67 J5.68 J5.73 J5.74 J5.79 J5.80 J5.85 J5.86 J5.91 J5.92 J5.97 J5.98 J8.2 J8.5 J8.8 J8.11 J8.17 J8.SH1 J8.SH2 J8.SH3 J8.SH4(SHIELD4) J9.1 J10.1 J10.2 J10.7 J10.8 J10.13 J10.14 J10.22 J10.23 J10.32 J10.33 J10.42 J10.43 J10.52 J10.53 J10.59 J10.60 J10.65 J10.66 J10.71 J10.74 J10.98 J11.SH1 J11.SH2 J11.SH3 J11.SH4(SHIELD4) J17.6(VSS) J17.11 J17.12 J17.13 J17.14 J17.15 J17.16 J23.1 J23.7 J23.18 J23.33 J23.39 J23.45 J23.51 J23.57 J23.63 J23.69 J23.75 J37.10 J38.2 J38.4 J38.6 J38.8 J38.10 J46.1 J47.A1 J47.A12 J47.B1 J47.B12 J48.2(SLEEVE) J48.3 J49.2 M1.1(MT1) MTH1.1(TP) MTH2.1(TP) MTH3.1(TP) MTH4.1(TP) MTH5.1(TP) Q14.S R2.2 R3.1 R4.2 R6.2 R7.2 R8.2 R10.2 R44.1 R45.1 R52.1 R64.2 R65.1 R84.2 R85.2 R360.1 R364.1 R366.1 R368.1 R372.1 R374.1 R384.1 R393.1 R394.1 R400.1 R403.2 R404.1 R408.2 SW8.9(B8) SW8.10 SW8.11 SW8.12 SW8.13 SW8.14 SW8.15 SW8.16 TP4.1(TP) TP5.1(TP) TP6.1(TP) TP7.1(TP) TP8.1(TP) TP9.1(TP) U1.5 U1.10 U2.2 U3.4 U4.3 U6.3 U6.8 U7.3 U7.8 U8.3 U9.2 U10.8 U10.9 U10.10 U10.EP U11.1 U11.4 U12.7 U12.9 U14.H U15.2 U15.5 U16.3 U16.13 U16.16 U16.17 U16.H U18.3(GND) U29.19 U29.22 U29.H U30.3 U33.2 U33.4 U33.5 U33.6 U33.7 U33.16 U33.19 U34.3 U36.3 U37.3 U38.3 U39.3 Y1.2 Y1.4(GND#4)
GND_EARTH: C180.2 J1.SH1 J1.SH2 J1.SH3 J1.SH4 J3.SH1 J3.SH2 J3.SH3 J3.SH4 J4.SH1 J4.SH2 J4.SH3 J4.SH4 J47.SH1 J47.SH2 J47.SH3 J47.SH4 R372.2
V3P3: C162.1 C165.1 C173.1 R347.1 R359.1 R365.1 R367.1 R369.1 U29.23(VDDD)
VBAT: J21.2 J23.2 J23.4 J23.72 J23.74
VBUS: C2.1 C3.1 C4.1 C5.1 C6.1 J3.1 J3.5(VBUS2) J4.1 J4.5(VBUS2) U2.6(OUT)
VBUS_FET_EN: R297.2 TP32.1(TP) U29.3
VBUS_MAX: R366.2 R367.2 U29.2
VBUS_MIN: R364.2 R365.2 U29.1
VBUS_OUT: C28.1 C29.1 C139.1 R390.1 U12.2(VIN) U29.11 U35.5 U35.6
VCCD: C175.1 U29.24
VCCD_17758174: C61.1 R94.1 U16.12
VDD_5V: C59.1 C60.1 J10.77 J10.79 J10.81 J10.83 J10.85 J10.87 R383.2 R405.1 U16.15
VDD_REG_5V: D28.A R393.2 R405.2
VDDD: C62.1 C63.1 R80.1 R94.2 R407.1 U16.24
VDDIO: J23.64 J36.2
BT_DBG_CTS: J23.67 J37.5
BT_DBG_RTS: J23.65 J37.4
BT_DBG_RX: J23.73 J37.7 R53.1
BT_DBG_TX: J23.71 J37.6 R88.1
BT_HOST_WAKE: J35.6 R86.2 U10.5
BT_HOST_WAKE_3P3: J23.20 R34.2
BT_NDIS: J10.91 SW8.4
BT_REG_ON_3P3: J23.54(W_DISABLE2# (I)(0/3.3V)) R25.2 R33.2 SW2.3 SW2.4(D) SW8.8
BT_USB_DN: J1.A7 J1.B7 U1.8 U34.2(IN2)
BT_USB_DP: J1.A6 J1.B6 U1.9 U34.1
CC1: C158.1 D18.K(CATHODE) J47.A5 U29.15
CC2: C159.1 D24.K(CATHODE) J47.B5 U29.14
CTS: R98.2 U16.22
EEPROM_NWP: J10.20 SW8.6
ETH_LEDG: J10.15 R14.1
ETH_LEDY: J10.17 R13.1
EXT_5V: D27.A D30.C(CATHODE) D31.C(CATHODE) J48.1 R394.2
EXT_LPO: U10.6 U11.2
EXT_LPO_3P3: R48.1 U10.11
FAULT: Q14.G R374.2 TP31.1(TP) U29.9
FET_GATE: D25.A R298.2 R321.2 U35.2 U35.4
FET_SRC: D25.C(CATHODE) R298.1 U35.1 U35.3(S1)
FLIP: R347.2 TP35.1(TP) U29.10
GLOBAL_EN: J10.99 SW8.1
GPIO2: J10.58 U10.3
GPIO3: J10.56 U10.4
GPIO4: J10.54 J23.42 TP38.1(TP)
GPIO5: J10.34 R37.2
GPIO6: J10.30 U15.3
GPIO6_3P3: R51.2 U15.4
GPIO7: J10.37 R39.2
GPIO8: J10.39 R57.1 R95.1
GPIO9: J10.40 R55.1 R96.1
GPIO10: J10.44 R53.2 R97.1
GPIO11: J10.38 R54.1 R98.1
GPIO12: J10.31 R86.1 R87.1
GPIO13: J10.28 R88.2 R89.2
GPIO14: J10.55 J30.3
GPIO15: J10.51 J30.1
GPIO16: J10.29 J30.5
GPIO17: J10.50 J30.7
GPIO18: J10.49 J25.1
GPIO19: J10.26 J25.3
GPIO20: J10.27 J25.5
GPIO21: J10.25 J25.7
GPIO22: J10.46 R28.2
GPIO23: J10.47 R29.2
GPIO24: J10.45 R30.2
GPIO25: J10.41 R32.2
GPIO26: J10.24 R35.2
GPIO27: J10.48 R36.2
GPIO_VREF: J10.78 SW9.2
HD1_M2_N: J23.5 R92.1
HD1_M2_P: J23.3 R93.1
HD1_N: R5.2 R92.2 U14.1
HD1_P: R9.1 R93.2 U14.2
HD1_PORT_N: J3.2 R5.1 U36.1
HD1_PORT_P: J3.3 R9.2 U36.2(IN2)
HD2_N: J3.6 U14.3 U37.1
HD2_P: J3.7 U14.4 U37.2(IN2)
HD3_N: J4.2 U14.6 U38.1
HD3_P: J4.3 U14.7 U38.2(IN2)
HD4_N: J4.6 U14.8 U39.1
HD4_P: J4.7 U14.9 U39.2(IN2)
HDMI0_CEC: J5.51 J8.13
HDMI0_CK_N: J5.90 J8.12
HDMI0_CK_P: J5.88 J8.10
HDMI0_D0_N: J5.84 J8.9
HDMI0_D0_P: J5.82 J8.7
HDMI0_D1_N: J5.78 J8.6
HDMI0_D1_P: J5.76 J8.4
HDMI0_D2_N: J5.72 J8.3
HDMI0_D2_P: J5.70 J8.1
HDMI0_HOTPLUG: J5.53 J8.19
HDMI0_SCL: J5.100 J8.15
HDMI0_SDA: J5.99 J8.16
HDMI_5V: C18.1 J8.18 U4.2(VOUT)
ID_SC: J10.35 TP2.1(TP)
ID_SD: J10.36 TP1.1(TP)
ISNK_COARSE: R368.2 R369.2 U29.5
ISNK_FINE: R359.2 R360.2 U29.6
LED1: J23.6 J37.8
LED2: J23.16 J37.9
M2_3.3V: C23.1 C30.1 C31.1 C32.1 C33.1 C34.1 J21.1 J37.1 L1.2 R25.1 R27.2 R38.1 R58.1 R70.2 SW5.2 U11.3(VDD)
M2_GPIO1: J23.59 J37.2
M2_GPIO2: J23.61 J37.3
NEXTRST: J10.100 U14.26
NLED_ACTIVITY: J10.21 R12.2
NOCS: U2.4 U14.13 U14.17 U14.19 U14.21
NPWR_LED: J10.95 U8.2
NRPIBOOT: J10.93 SW8.5
PCIE_CLK_N: J5.12 R47.2
PCIE_CLK_NREQ_3P3: J5.2 R50.2
PCIE_CLK_P: J5.10 R46.2
PCIE_NRST_3P3: J5.9 R49.1
PCIE_PME_L: J23.55 R51.1
PCIE_RX_N: J5.18 R43.2
PCIE_RX_P: J5.16 R42.2
PCIE_TX_N: J5.24 R41.2
PCIE_TX_P: J5.22 R40.2
PERI_5V: C1.1 C17.1 D27.C D28.C J9.2 U2.1 U4.1
PWM0_0: R82.1 R87.2
PWM0_1: R83.1 R89.1
PWR1: U2.3 U14.12
RTS: R97.2 U16.21
RUN_PG: J10.92 J49.1 SW8.2
RXD: R95.2 U16.1
SCL0: J10.80 U3.2
SD_CLK: J10.57 R18.1
SD_CMD: J10.62 R17.1
SD_DAT0: J10.63 R19.1
SD_DAT1: J10.67 R20.1
SD_DAT2: J10.69 R15.1
SD_DAT3: J10.61 R16.1
SD_DET: J10.76 R23.1
SD_PWR: C20.1 J17.4 U9.1(VOUT)
SD_PWR_ON: J10.75 R24.2 U9.4
SDA0: J10.82 U3.1
TR0_TAP: J11.P11 TP12.1(TP)
TR1_TAP: J11.P12 TP10.1(TP)
TR2_TAP: J11.P13 TP11.1(TP)
TR3_TAP: J11.P14 TP13.1(TP)
TRD0_N: J10.10 J11.P2 U7.4
TRD0_P: J10.12 J11.P1 U7.5
TRD1_N: J10.6 J11.P6 U7.1
TRD1_P: J10.4 J11.P3 U7.2
TRD2_N: J10.9 J11.P8 U6.5
TRD2_P: J10.11 J11.P7 U6.4
TRD3_N: J10.5 J11.P10 U6.2
TRD3_P: J10.3 J11.P9 U6.1
TXD: R96.2 U16.23
UART_CTS: J23.36 J30.8(P8) SW4.3 SW4.4(D)
USB2_N: J5.3 U1.4
USB2_P: J5.5 U1.3
USB-UART_VBUS: C144.1 C172.2 D21.1 D26.A J47.A4 J47.A9 J47.B4 J47.B9(VBUS_4) R302.1 U29.18 U35.7 U35.8
USB_PWR: C41.2 D29.K(CATHODE) D32.C(CATHODE) J1.A4 J1.A9 J1.B4 J1.B9(VBUS_4) R1.1
USBOTG: J5.1 R1.2 R2.1 U1.2
USBRPI_DM: J47.A7 J47.B7 U16.11 U30.2(IN2)
USBRPI_DP: J47.A6 J47.B6 U16.10 U30.1
WL_HOST_WAKE: J23.21 J35.5 R37.1
WL_JTAG_TCK: J23.46 J38.9(P9)
WL_JTAG_TDI: J23.40 J38.3
WL_JTAG_TDO: J23.38 J38.5
WL_JTAG_TMS: J23.48 J38.7
WL_JTAG_TRST: J23.44 J38.1
WL_NDIS: J10.89 SW8.3
WL_REG_ON_3P3: J23.56 R31.2 R38.2 SW3.3 SW3.4(D) SW8.7
WL_UART_CTS: J23.66 J35.3 R54.2
WL_UART_RTS: J23.62 J35.4
WL_UART_RXD: J23.70 J35.2 R57.2
WL_UART_TXD: J23.68 J35.1 R55.2
N17441828: R4.1 U2.5
N17442267: U1.7 U14.31
N17442276: U1.6 U14.30
N17442959: C8.1 U14.32(XTALOUT) Y1.3
N17443006: C7.1 U14.33 Y1.1
N17443696: R3.2 U14.35
N17444208: R6.1 U14.24
N17444213: R7.1 U14.22
N17444218: R8.1 U14.28
N17444223: R10.1 U14.25
N17463017: C53.1 J11.P4 J11.P5
N17463374: J11.P16 R13.2
N17463377: J11.P18 R14.2
N17465158: D14.C(CATHODE) R21.1
N17465213: R21.2 U8.4(Y)
N17469381: J17.9 R23.2
N17469410: J17.10 R22.2
N17494894: J23.53 R50.1
N17494904: J23.47 R46.1
N17494909: J23.49 R47.1
N17494920: J23.35 R40.1
N17494923: J23.37 R41.1
N17494926: J23.41 R42.1
N17494929: J23.43 R43.1
N17499052: J23.9 R28.1
N17499057: J23.11 R29.1
N17499218: J23.13 R30.1
N17499237: J23.15 R32.1
N17499256: J23.17 R35.1
N17499275: J23.19 R36.1
N17499655: J23.52 R49.2
N17504773: D15.A R58.2
N17512684: R61.2 R62.2 R64.1 U12.5
N17512777: C35.1 U12.4
N17512799: C27.1 U12.1
N17512803: C27.2 R60.1
N17512813: L1.1 R60.2 U12.8
N17512829: C229.1 R63.1 U12.6
N17540958: C21.2 R26.1 U10.1 U10.2 U10.7 U10.15
N17540970: C22.1 R27.1 U10.16(VCCB)
N17541044: R31.1 U10.14
N17541046: R33.1 U10.13
N17541095: R34.1 U10.12
N17548832: J23.8 J25.2
N17548852: J23.10 J25.4
N17549259: J23.50 R48.2
N17549874: R44.2 SW2.1 SW2.2
N17549924: R45.2 SW3.1 SW3.2
N17560700: J23.23 R39.1
N17563208: R52.2 SW4.1 SW4.2
N17565806: J23.12 J25.6
N17565868: J23.14 J25.8(P8)
N17568318: J17.1 R15.2
N17568347: J17.2 R16.2
N17568375: J17.3 R17.2
N17568415: J17.5 R18.2
N17569067: J17.7 R19.2
N17569095: J17.8 R20.2
N17573256: R62.1 SW5.3(B2)
N17579667: J9.4 U3.5
N17579869: J9.3 R11.2 U3.6
N17596444: J23.34 J30.6
N17596453: J23.32 J30.4
N17596462: J23.22 J30.2
N17603435: C52.2 R69.1 U15.1
N17603462: C51.1 R70.1 U15.6(VCCB)
N17711071: R61.1 SW5.1
N17724540: C55.1 C57.1 R82.2 R85.1
N17724607: C56.1 C58.1 R83.2 R84.1
N17727243: C57.2 J46.3 U18.2
N17727252: C58.2 J46.2 U18.1
N17754557: TP33.1(TP) U29.7
N17754588: TP34.1(TP) U29.8
N17760781: C139.2 C144.2 R297.1 R302.2 R321.1
N17761001: Q14.D R373.1
N17761005: D26.C(CATHODE) R373.2
N17763457: C210.1 U33.14
N17763461: C210.2 L5.1 U33.13
N17763467: C197.2 L5.2 U33.12
N17763564: C197.1 U33.11
N17763650: C185.P C191.1 C192.1 C195.1 R383.1 R399.1 U33.3
N17763766: C224.2 U33.15 U33.17
N17763790: R399.2 R403.1 U33.21
N17763820: C225.2 U33.18
N17763850: R384.2 U33.9
N17767575: J1.A5 R404.2
N17767581: J1.B5 R65.2
N17769646: TP37.1(TP) U29.12
N17769649: TP36.1(TP) U29.13
N17801368: J5.6 R406.2
N17848252: R408.1 SW10.1
N17848257: R400.2 SW10.5
N17849598: R398.2 SW10.7
N17880549: C36.1 R63.2
N174866950: D13.C(CATHODE) R12.1

Pads without a net: J1 A2 A3 A8 A10 A11 B2 B3 B8 B10 B11; J5 4 11 15 17 21 23 27 28 29 30 33 34 35 36 39 40 41 42 43 45 46 47 48 49 52 54 57 58 59 60 63 64 65 66 69 71 75 77 81 83 87 89 93 94 95 96; J8 14; J10 16 18 19 64 68 70 72 73 94 96 97; J23 58 60; J46 4 5 6; J47 A2 A3 A8 A10 A11 B2 B3 B8 B10 B11; NOREF#4 1; NOREF#20 1; NOREF#24 1; NOREF#27 1; NOREF#36 1; NOREF#43 1; U3 7 8; U6 6 7 9 10; U7 6 7 9 10; U8 1; U9 3; U14 11 14 16 18 20 34; U16 2 4 5 6 7 8 9 14 18 19 20; U29 4 16 17 20 21; U33 8 10

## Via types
v1: diameter 0.5, hole 0.25, TOP to BOTTOM, 2620 vias

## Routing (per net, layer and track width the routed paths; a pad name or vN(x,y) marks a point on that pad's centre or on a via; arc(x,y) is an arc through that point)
1.8V: length 199.4
  TOP w0.203: J10.88 111.14,30.54 111.32,30.36 v1(111.79,30.36) ; J10.90 111.03,30.14 111.37,29.81 v1(112.29,29.81)
  TOP w0.381: SW9.1 v1(97.77,20.17)
  TOP w0.508: v1(50.32,71.3) 50.32,72.49 48.34,74.47 48.34,82.68 v1(47.57,83.44) ; v1(87.12,43.26) 87.12,45.42 v1(86.87,45.67) 86.51,46.02 86.51,52.22 83.46,55.27 82.3,55.27 81.03,56.54 81.03,60.3 80.72,60.61 v1(80.26,60.61) ; v1(97.79,12.67) 97.79,12.65 R26.2
  L03_PWR w0.381: v1(47.57,83.44) 47.57,86.51 45.49,88.6 31.04,88.6 30.7,88.93 24.11,88.93 22.81,87.63 v1(22.81,86.39)
  L03_PWR w0.508: J36.1 94.6,25.22 96.09,26.71 ; 96.09,26.71 96.09,32.11 95.17,33.02 87.78,33.02 87.22,33.58 87.22,42.27 87.12,42.37 v1(87.12,43.26) ; 96.09,26.71 96.99,25.81 101.27,25.81 101.85,26.39 103.2,26.39 103.84,25.76 103.84,25.12 ; 103.84,25.12 103.84,22.31 103.24,21.72 100.69,21.72 99.13,20.17 v1(97.77,20.17) 97.66,20.06 97.66,18.72 98.4,17.98 98.4,16.88 v1(98.09,16.57) ; 103.84,25.12 105.91,25.12 106.34,25.55 107.03,25.55 111.38,29.89
  BOTTOM w0.381: v1(50.32,71.3) 50.32,69.77 51.64,68.45 51.64,66.73 53.7,64.67 53.7,59.87 52.58,58.75 52.58,51.98 56.04,48.52 56.76,48.52 57.78,47.5 57.78,46.15 58.59,45.34 65.2,45.34 65.58,44.96 67.68,44.96 68.41,44.22 72.11,44.22 72.59,43.74 74.4,43.74 74.98,44.32 77.2,44.32 77.96,45.09 80.25,45.09 80.74,44.59 81.38,44.59 82.46,45.67 v1(86.87,45.67) ; R80.2 v1(22.81,86.39)
  BOTTOM w0.508: v1(97.79,12.67) 98.58,13.46 98.58,14.78 98.09,15.27 v1(98.09,16.57) ; R69.2 v1(80.26,60.61)
3.3V: length 205.5
  TOP w0.203: v1(112.79,31.6) 112.54,31.34 J10.84 ; v1(113.26,31.17) 113.04,30.94 J10.86 ; D14.A 135.03,9.34 U8.5 133.62,8.1 136.26,5.46 D13.A
  TOP w0.381: v1(53.21,67.08) 58.29,67.08 59.72,65.66 v1(59.72,64.54) ; SW9.3 v1(101.27,22.83) ; C19.1 R11.1 ; C19.1 v1(143.17,69.11) 145.57,69.11 147.02,67.67 147.02,58.9 147.84,58.07 147.84,53.58 150.45,50.97 150.45,49.84 149.22,48.62 R406.1 ; C19.1 143.17,71.59 142.88,71.89 U3.3 ; U8.5 133.62,9.79 134.67,10.85 134.67,12.64 133.88,13.42 v1(133.88,13.94) v1(131.95,13.94) ; SW10.3 v1(24.4,70.22)
  L03_PWR w0.381: 105,87.2 J11.P15 103.16,85.36 ; 92.42,85.36 J11.P17 94.26,87.2 ; v1(53.21,67.08) 48.92,71.37 48.92,73.46 48.29,74.09 48.29,81.19 47.9,81.57 47.36,81.57 46.94,81.99 46.94,85.98 44.96,87.96 32.36,87.96 31.11,86.71 28.81,86.71 27.76,87.76 24.56,87.76 v1(23.83,87.02) 25.04,87.02 25.72,86.34 25.72,80.71 25.02,80.01 25.02,78.41 22.63,76.02 22.63,72 v1(24.4,70.22)
  L03_PWR w0.508: J11.P17 93.34,87.7 93.37,87.73 ; J11.P17 94.87,86.28 94.89,86.26 ; J11.P17 92.07,86.28 92.05,86.26 ; J11.P17 93.34,84.76 93.32,84.73 ; J11.P15 104.08,87.73 104.09,87.73 ; J11.P15 104.08,84.89 104.09,84.89 ; J11.P15 105.69,86.28 105.71,86.31 ; J11.P15 102.85,86.28 102.82,86.31 ; 119.96,77.27 126.09,71.15 130.76,71.15 132.79,69.11 v1(143.17,69.11)
  BOTTOM w0.254: U1.1 v1(74.64,62.07)
  BOTTOM w0.305: v1(63,67.96) 62.99,67.98 C11.1 62.32,67.56 62.47,67.41 U14.10 ; U14.36 62.47,60.87 62.24,60.64 60.34,60.64 C16.1 ; U14.15 64.97,67.36 65.31,67.7 C12.1 65.93,68.13 v1(66.07,68) ; C15.1 59.35,63.9 U14.5 ; v1(69.01,64.79) 68.95,64.74 C13.1 68.4,64.13 68.17,63.9 U14.23 ; U14.29 65.97,60.48 66.55,59.89 C14.1 ; U14.27 67.54,61.9 68.16,61.28 C10.1 C9.1
  BOTTOM w0.381: C16.1 59.25,60.3 59.25,60.77 59.79,61.32 v1(61.32,61.32) ; C15.1 59.29,64.54 v1(59.72,64.54) ; R22.1 133.88,15.03 v1(133.88,13.94) ; C14.1 66.1,59.85 v1(65.93,59.68) ; C9.1 v1(70.17,61.28) ; v1(23.83,87.02) R407.2
  BOTTOM w0.508: v1(130.27,24.17) R24.1 130.26,23.29 U9.5
3V3_EN: length 65.7
  TOP w0.127: v1(33.35,28.68) 32.89,28.22 30.68,28.22 30.23,28.68 16.81,28.68 15.65,29.84 v1(15.65,31.11) ; SW10.2 18.9,66.47 16.64,64.21 v1(14.76,64.21)
  BOTTOM w0.127: v1(15.65,31.11) 14.1,32.66 14.1,38.82 14.1,38.82 14.1,63.55 v1(14.76,64.21) ; U12.3 32.15,27.48 v1(33.35,28.68)
5V_EN: length 37.1
  TOP w0.127: SW10.6 18.9,72.42 20.09,71.22 20.09,66.88 28.47,58.5 28.47,55.27 v1(30.96,52.78)
  BOTTOM w0.127: v1(30.96,52.78) 31.78,52.78 32.79,51.77 32.79,47.35 33.81,46.33 35.7,46.33 36.37,47 U33.20
5V_IN: length 43.1
  TOP w0.381: R398.1 21.42,75.67 v1(25.86,75.67)
  BOTTOM w0.381: C228.P 36.53,68.57 35.23,69.88 31.67,69.88 31.01,69.22 26.95,69.22 25.86,70.31 v1(25.86,75.67) ; C228.P 36.53,65.32 ; C228.P 38.56,66.4 ; 37.27,56.7 C227.P ; C227.P 37.27,58.87 ; C227.P 39.3,57.78 ; R390.2 41.75,64.99 ; R390.2 39.79,64.99 ; R390.2 40.77,64.06 ; C215.1 38.22,49.35 C214.1 ; 38.22,53.68 C216.1 39,52.7 ; C214.1 38.72,49.3 ; C214.1 38.17,48.77
  BOTTOM w0.508: C216.1 C215.1 39.12,50.8 ; U33.1 38.68,48.69
GND: length 1751.2
  TOP w0.178: v1(109.02,45.36) 109.04,45.34 J10.14 ; J5.8 144.89,46.54 v1(145.29,46.95)
  TOP w0.203: 145.01,41.74 J5.32 143.12,41.74 ; J10.42 109.13,39.74 v1(109.11,39.76) ; 143.12,29.74 J5.92 145,29.74 v1(145.12,29.62) ; 142.3,34.54 J5.67 140.53,34.54 ; v1(145.1,28.82) 144.83,28.54 J5.98 ; 142.3,46.54 J5.7 139.56,46.54 v1(139.52,46.51) ; v1(109.13,41.89) 109.27,41.74 J10.32 111.84,41.74 v1(111.88,41.79) ; v1(111.2,47.85) 111.2,47.81 111.14,47.74 J10.2 ; v1(106.38,47.85) 106.49,47.74 J10.1 ; 145.01,38.14 J5.50 143.12,38.14 ; 142.3,36.94 J5.55 140.71,36.94 140.54,36.78 ; v1(108.66,36.5) 108.3,36.14 J10.59 ; 142.3,41.74 J5.31 v1(140.36,41.74) ; v1(140.17,45.44) 140.27,45.34 J5.13 142.3,45.34 ; 143.12,39.34 J5.44 145.01,39.34 ; J10.65 108.5,34.94 108.51,34.95 ; 142.3,30.94 J5.85 v1(140.36,30.94) ; 143.12,36.94 J5.56 145.01,36.94 ; v1(108.71,42.98) 108.35,43.34 J10.23 106.79,43.34 106.28,43.86 106.24,43.86 v1(106.17,43.79) ; 145.01,34.54 J5.68 143.12,34.54 ; v1(145.19,32.14) J5.80 143.12,32.14 ; 140.53,42.94 J5.25 142.3,42.94 ; v1(108.51,37.66) 108.19,37.34 J10.53 106.04,37.34 v1(105.91,37.48) ; v1(111.4,46.54) J10.8 ; 143.12,44.14 J5.20 144.99,44.14 145.07,44.22 ; 143.12,40.54 J5.38 145.01,40.54 ; 111.05,43.94 110.85,43.74 J10.22 109.28,43.74 v1(109.12,43.59) ; 143.12,30.94 J5.86 145.05,30.94 v1(145.08,30.91) ; J10.13 v1(106.17,45.34) ; J10.74 111.12,33.34 v1(111.3,33.53) ; v1(145.13,42.44) 145.13,42.73 144.92,42.94 J5.26 143.12,42.94 ; J10.52 109.18,37.74 v1(109.13,37.79) ; 142.3,35.74 J5.61 140.53,35.74 ; 142.3,29.74 J5.91 v1(140.28,29.74) 140.16,29.62 139.9,29.62 139.85,29.57 139.09,29.57 v1(138.13,28.6) ; v1(106.26,46.54) J10.7 ; 142.3,32.14 J5.79 140.22,32.14 v1(140.21,32.16) ; 142.3,33.34 J5.73 140.49,33.34 v1(140.38,33.45) ; v1(108.61,41.34) J10.33 106.82,41.34 105.92,42.25 105.53,42.25 105.05,42.72 104.5,42.72 104.48,42.74 v1(104.44,42.74) ; v1(109.06,28.7) 109.21,28.54 J10.98 111.18,28.54 v1(111.35,28.71) ; J10.60 111.33,36.14 v1(111.4,36.22) ; v1(111.24,34.96) 111.23,34.94 J10.66 109.33,34.94 109.19,35.08 v1(108.97,35.08) ; v1(145.14,45.36) 145.11,45.34 J5.14 143.12,45.34 ; v1(105.21,39.62) 105.45,39.87 106.13,39.87 106.66,39.34 J10.43 108.41,39.34 v1(108.52,39.23) ; 142.3,40.54 J5.37 v1(140.36,40.54) ; v1(140.06,28.04) 140.56,28.54 J5.97 v1(142.4,28.54) ; 143.12,33.34 J5.74 v1(145.24,33.34) ; 140.53,44.14 J5.19 142.3,44.14 ; 143.12,35.74 J5.62 145.01,35.74 ; v1(106.26,33.61) 106.39,33.74 J10.71 108.47,33.74 v1(108.56,33.66) ; J5.8 143.12,46.54
  TOP w0.254: v1(93.07,17.3) 93.35,17.01 U10.9 93.35,15.08 v1(93.6,14.83) 93.85,15.08 U10.8 v1(93.85,17.32) ; C22.2 93.32,10.47 v1(93.26,10.41) ; 42.06,79.93 J47.A1 42.06,82.18 J47.B12 ; v1(72.09,45.39) 72.07,45.38 U11.4 ; C53.2 98.32,68.33 v1(98.37,68.28) ; 36.56,79.92 J47.A12 36.62,81.2 36.62,82.12 J47.B1 ; U10.10 92.02,16.08 v1(91.69,16.41) ; U11.1 71.66,45.2 v1(71.42,45.44) ; v1(47.14,46.94) 47.62,46.46 J23.7 ; J1.B1 117.02,82.12 117.02,81.3 116.99,81.24 116.99,81.07 J1.A12 ; U30.3 38.37,78.01 v1(37.95,78.44)
  TOP w0.305: v1(55.61,46.78) 55.62,46.77 J23.39 v1(55.62,44.32) ; U7.3 v1(100.69,67.44) ; v1(57.13,46.78) 57.12,46.77 J23.45 v1(57.12,44.32) ; v1(94.59,67.51) 94.69,67.61 U6.3 ; v1(61.62,44.29) J23.63 61.62,46.68 v1(61.69,46.74) ; 60.12,44.4 J23.57 60.12,46.74 v1(60.14,46.76) ; v1(46.12,44.25) J23.1 46.12,46.38 45.87,46.63 v1(45.42,46.63) ; J23.75 64.62,44.4 ; v1(40.41,72.57) 40.19,72.34 U29.22 ; v1(40.41,73.58) 40.15,73.84 U29.19 ; J8.11 v1(137.82,81.66) ; 116.96,79.93 J1.A12 116.81,80.77 116.61,80.77 116.36,80.52 ; J1.B12 122.46,82.18 J1.A1 ; J8.8 v1(136.31,81.68) ; J1.A1 122.61,80.77 122.91,80.77 123.04,80.64 ; J1.A1 122.46,79.99 ; v1(50.37,36.8) J23.18 v1(50.37,39.17) ; J8.2 v1(133.31,81.63) ; 54.12,44.4 J23.33 54.12,46.6 ; v1(100.69,69.75) U7.8 ; v1(140.82,81.64) J8.17 140.82,77.42 v1(140.87,77.37) ; J23.7 47.62,44.17 v1(47.6,44.15) ; U6.8 v1(94.69,69.93) ; 63.12,46.74 J23.69 v1(63.12,44.32) ; 58.62,44.4 J23.51 58.62,46.77 v1(58.63,46.78) ; J8.5 v1(134.81,81.69)
  TOP w0.381: M1.1 56.84,15.45 ; M1.1 52.72,14.65 ; M1.1 58.82,13.46 ; M1.1 58.02,14.65 ; J38.2 27.34,36.4 ; J38.2 26.24,35.29 ; J38.2 25.13,36.4 ; J38.2 26.24,37.5 ; 124.76,72.81 D32.A ; D32.A 126.39,73.89 ; D32.A 124.76,74.97 ; 16.63,85.89 J48.2 ; J48.2 18.88,84.78 ; J48.2 21.14,85.89 ; J48.2 18.88,86.99 ; 74.24,77.59 J3.8 ; J3.8 73.21,78.62 ; J3.8 75.27,78.62 ; J3.8 74.24,79.65 ; 88.24,79.17 J11.SH2 ; J11.SH2 90.95,79.17 ; J11.SH2 89.59,77.81 ; C22.2 93.97,11.11 v1(94.06,11.2) ; J38.8 19.72,36.4 ; J38.8 17.51,36.4 ; J38.8 18.62,35.29 ; J38.8 18.62,37.5 ; J49.2 100.88,31.18 ; J49.2 99.78,30.07 ; J49.2 100.88,28.97 ; J49.2 101.99,30.07 ; D18.A 39.37,76.17 39.07,75.87 ; D18.A 39.89,75.49 ; D18.A 40.47,76.17 ; SW8.16 107.92,3.35 ; SW8.16 107.26,2.45 ; SW8.16 107.26,4.26 ; R400.1 16.41,76.56 v1(16.43,76.58) ; 86.47,64.82 TP8.1 85.09,66.2 ; J11.SH3 103.16,84.46 ; J11.SH3 103.16,79.98 ; J11.SH3 100.92,82.22 ; TP9.1 152.66,25.39 ; TP9.1 151.28,26.77 ; TP9.1 149.9,25.39 ; TP9.1 151.28,24.01 ; 36.2,83.19 36.2,82.55 J47.B1 ; J8.SH4 131.17,86.58 ; J8.SH4 128.96,86.58 ; J8.SH4 130.07,84.87 ; J8.SH4 130.07,88.29 ; J1.B1 116.56,82.58 116.56,83.06 ; 74.24,74.89 J3.4 ; J3.4 74.24,76.95 ; J3.4 75.27,75.92 ; J3.4 73.21,75.92 ; TP4.1 11.03,58.83 ; TP4.1 9.65,57.45 ; TP4.1 9.65,60.21 ; TP4.1 8.27,58.83 ; 53.98,78.62 J4.8 ; J4.8 55.01,77.59 ; J4.8 55.01,79.65 ; J4.8 56.04,78.62 ; 150.75,12.43 MTH1.1 ; MTH1.1 150.75,19.64 ; MTH1.1 147.15,16.03 ; 6.35,82.25 MTH2.1 ; MTH2.1 9.95,85.85 ; MTH2.1 6.35,89.46 ; MTH2.1 2.74,85.85 ; TP7.1 94.02,8.54 ; TP7.1 91.26,8.54 ; TP7.1 92.64,9.92 ; TP7.1 92.64,7.16 ; 105.99,4.26 SW8.15 105.99,2.45 ; J1.B12 122.8,82.52 122.8,83.22 ; J8.SH1 145.67,80.62 ; J8.SH1 143.46,80.62 ; J8.SH1 144.56,78.61 ; J8.SH1 144.56,82.63 ; 102.18,4.26 SW8.12 102.18,2.45 ; J8.SH3 144.56,88.29 ; J8.SH3 144.56,84.87 ; J8.SH3 143.46,86.58 ; J8.SH3 145.67,86.58 ; U3.4 140.96,71.24 140.67,70.94 v1(140.67,70.21) ; MTH5.1 73.37,53.92 ; MTH5.1 66.16,53.92 ; MTH5.1 69.76,57.52 ; 43.91,76.17 D24.A ; D24.A 44.49,75.49 ; D24.A v1(45.44,76.17) ; D24.A 44.49,76.85 ; 3.16,15.95 TP6.1 ; TP6.1 4.54,17.33 ; TP6.1 3.16,18.71 ; TP6.1 1.78,17.33 ; 131.83,11.24 U8.3 ; U8.3 132.32,10.66 ; U8.3 132.32,11.82 ; 36.38,70.73 C175.2 37.04,70 ; 97.72,3.35 SW8.9 ; SW8.9 98.37,4.26 ; SW8.9 98.37,2.45 ; 14.08,80.38 J48.3 ; J48.3 12.98,82.64 ; J48.3 14.08,84.9 ; J48.3 15.19,82.64 ; 100.91,2.45 SW8.11 100.91,4.26 ; MTH4.1 14.66,16.03 ; MTH4.1 11.05,12.43 ; MTH4.1 7.45,16.03 ; MTH4.1 11.05,19.64 ; J38.6 21.16,37.5 ; J38.6 20.05,36.4 ; J38.6 21.16,35.29 ; J38.6 22.26,36.4 ; v1(63.16,46.78) 63.12,46.74 ; 147.15,85.82 MTH3.1 150.75,82.21 ; D29.A 124.29,77.06 ; D29.A 124.87,76.38 ; D29.A 124.29,75.7 ; D29.A 123.71,76.38 ; 42.47,83.01 42.47,82.59 J47.B12 ; J38.10 17.18,36.4 ; J38.10 14.97,36.4 ; J38.10 16.08,35.29 ; J38.10 16.08,37.5 ; J4.4 55.01,76.95 ; J4.4 53.98,75.92 ; J4.4 55.01,74.89 ; J4.4 56.04,75.92 ; C165.2 v1(37.8,73.63) ; J8.SH2 130.07,82.63 ; J8.SH2 130.07,78.61 ; J8.SH2 128.96,80.62 ; J8.SH2 131.17,80.62 ; 99.64,4.26 SW8.10 99.64,2.45 ; 123.9,68.96 C41.1 ; C41.1 124.83,70.59 ; C41.1 123.9,72.22 ; C41.1 122.97,70.59 ; 104.72,4.26 SW8.14 104.72,2.45 ; D21.2 25.99,79.31 ; D21.2 25.99,76.45 ; D21.2 24.46,77.88 ; 150.4,70.93 J9.1 ; J9.1 151.65,72.19 ; J9.1 151.65,69.68 ; J9.1 152.91,70.93 ; TP5.1 53.63,71.59 ; TP5.1 52.25,70.21 ; TP5.1 53.63,68.83 ; TP5.1 55.01,70.21 ; 119.23,76.54 U34.3 ; U34.3 120.19,76.54 ; U34.3 119.71,76.03 ; J11.SH4 91.73,84.46 ; J11.SH4 91.73,79.98 ; J11.SH4 93.96,82.22 ; 32.55,5.67 D15.C ; D15.C 33.28,4.94 ; D15.C 33.28,6.4 ; 105.29,77.81 J11.SH1 ; J11.SH1 103.94,79.17 ; J11.SH1 106.65,79.17 ; J37.10 4.2,54.78 ; J37.10 3.1,53.68 ; J37.10 3.1,55.89 ; 73.55,44.66 C23.2 73.02,45.21 ; 22.59,36.4 J38.4 ; J38.4 23.7,37.5 ; J38.4 23.7,35.29 ; J38.4 24.8,36.4 ; v1(117.37,76.4) 117.14,76.64 R65.1 ; C173.2 v1(36.7,73.71) ; 141.74,69.79 C19.2 ; C19.2 142.32,69.26 ; C19.2 142.32,70.32 ; R368.1 v1(27.13,74.57) ; 103.45,4.26 SW8.13 103.45,2.45 ; R360.1 v1(27.16,70.05) ; C162.2 36.09,73.22 ; C162.2 34.63,73.22 ; C162.2 35.36,73.87 ; R366.1 v1(30.56,70.05) ; R408.2 15.44,67.11 v1(15.49,67.06) ; R404.1 v1(125.91,75.74) ; C20.2 v1(125.14,2.71) ; R364.1 v1(30.58,74.57)
  TOP w0.508: D15.C v1(34.28,5.67) ; C21.1 v1(97.64,13.53)
  TOP w1.27: M1.1 57.95,12 59.15,13.2 ; M1.1 55.37,16.27 ; M1.1 52.73,12 51.43,13.3
  L02_GND w0.381: J8.SH4 130.07,88.29 ; J8.SH4 131.17,86.58 ; J8.SH4 130.07,84.87 ; J8.SH4 128.96,86.58 ; 150.75,82.21 MTH3.1 147.15,85.82 ; TP5.1 53.63,71.59 ; TP5.1 55.01,70.21 ; TP5.1 53.63,68.83 ; TP5.1 52.25,70.21 ; TP9.1 152.66,25.39 ; TP9.1 151.28,24.01 ; TP9.1 149.9,25.39 ; TP9.1 151.28,26.77 ; MTH1.1 150.75,19.64 ; MTH1.1 147.15,16.03 ; MTH1.1 150.75,12.43 ; J9.1 151.65,72.19 ; J9.1 152.91,70.93 ; J9.1 150.4,70.93 ; J9.1 151.65,69.68 ; J38.8 18.62,37.5 ; J38.8 17.51,36.4 ; J38.8 18.62,35.29 ; J38.8 19.72,36.4 ; 105.29,77.81 J11.SH1 ; J11.SH1 106.65,79.17 ; J11.SH1 103.94,79.17 ; 2.74,85.85 MTH2.1 ; MTH2.1 9.95,85.85 ; MTH2.1 6.35,82.25 ; MTH2.1 6.35,89.46 ; TP7.1 94.02,8.54 ; TP7.1 92.64,7.16 ; TP7.1 92.64,9.92 ; TP7.1 91.26,8.54 ; 8.27,58.83 TP4.1 ; TP4.1 9.65,57.45 ; TP4.1 9.65,60.21 ; TP4.1 11.03,58.83 ; 121.93,81.65 J1.B12 121.83,82.23 ; J38.4 24.8,36.4 ; J38.4 23.7,35.29 ; J38.4 22.59,36.4 ; J38.4 23.7,37.5 ; 100.88,28.97 J49.2 ; J49.2 101.99,30.07 ; J49.2 99.78,30.07 ; J49.2 100.88,31.18 ; 73.21,75.92 J3.4 ; J3.4 75.27,75.92 ; J3.4 74.24,74.89 ; J3.4 74.24,76.95 ; 144.56,84.87 J8.SH3 ; J8.SH3 144.56,88.29 ; J8.SH3 145.67,86.58 ; J8.SH3 143.46,86.58 ; 55.01,77.59 J4.8 ; J4.8 55.01,79.65 ; J4.8 56.04,78.62 ; J4.8 53.98,78.62 ; 18.88,84.78 J48.2 ; J48.2 18.88,86.99 ; J48.2 16.63,85.89 ; J48.2 21.14,85.89 ; J3.8 74.24,79.65 ; J3.8 74.24,77.59 ; J3.8 75.27,78.62 ; J3.8 73.21,78.62 ; M1.1 58.82,13.46 ; M1.1 55.37,15.61 ; M1.1 52.72,14.65 ; M1.1 56.84,15.45 ; 3.1,53.68 J37.10 ; J37.10 1.99,54.78 ; J37.10 4.2,54.78 ; J37.10 3.1,55.89 ; 55.01,74.89 J4.4 ; J4.4 53.98,75.92 ; J4.4 56.04,75.92 ; J4.4 55.01,76.95 ; TP8.1 86.47,64.82 ; TP8.1 85.09,63.44 ; TP8.1 85.09,66.2 ; TP8.1 83.71,64.82 ; J8.SH1 145.67,80.62 ; J8.SH1 143.46,80.62 ; J8.SH1 144.56,82.63 ; J8.SH1 144.56,78.61 ; 25.13,36.4 J38.2 ; J38.2 26.24,37.5 ; J38.2 26.24,35.29 ; J38.2 27.34,36.4 ; 14.97,36.4 J38.10 ; J38.10 17.18,36.4 ; J38.10 16.08,37.5 ; J38.10 16.08,35.29 ; J38.6 22.26,36.4 ; J38.6 21.16,35.29 ; J38.6 20.05,36.4 ; J38.6 21.16,37.5 ; 117.59,82.23 J1.B1 116.33,82.81 ; 91.73,79.98 J11.SH4 ; J11.SH4 93.96,82.22 ; J11.SH4 91.73,84.46 ; TP6.1 3.16,18.71 ; TP6.1 1.78,17.33 ; TP6.1 3.16,15.95 ; TP6.1 4.54,17.33 ; 35.93,82.81 J47.B1 37.19,82.23 ; 7.45,16.03 MTH4.1 ; MTH4.1 11.05,19.64 ; MTH4.1 11.05,12.43 ; MTH4.1 14.66,16.03 ; 66.16,53.92 MTH5.1 ; MTH5.1 73.37,53.92 ; MTH5.1 69.76,50.31 ; MTH5.1 69.76,57.52 ; J8.SH2 131.17,80.62 ; J8.SH2 128.96,80.62 ; J8.SH2 130.07,82.63 ; J8.SH2 130.07,78.61 ; J48.3 14.08,84.9 ; J48.3 14.08,80.38 ; J48.3 12.98,82.64 ; J48.3 15.19,82.64 ; 89.59,77.81 J11.SH2 ; J11.SH2 88.24,79.17 ; J11.SH2 90.95,79.17 ; 41.53,81.65 J47.B12 41.43,82.23 ; 103.16,79.98 J11.SH3 ; J11.SH3 103.16,84.46 ; J11.SH3 100.92,82.22
  L02_GND w1.27: 51.82,15.49 55.31,12 M1.1 58.61,15.24
  L03_PWR w0.381: 73.21,75.92 J3.4 ; J3.4 75.27,75.92 ; J3.4 74.24,76.95 ; 16.63,85.89 J48.2 ; J48.2 18.88,84.78 ; J48.2 18.88,86.99 ; J48.2 21.14,85.89 ; 3.16,15.95 TP6.1 ; TP6.1 4.54,17.33 ; TP6.1 1.78,17.33 ; TP6.1 3.16,18.71 ; 150.4,70.93 J9.1 ; J9.1 151.65,72.19 ; J9.1 152.91,70.93 ; J9.1 151.65,69.68 ; J38.8 18.62,37.5 ; J38.8 17.51,36.4 ; J38.8 19.72,36.4 ; J38.8 18.62,35.29 ; 117.59,82.23 J1.B1 116.33,82.81 ; MTH2.1 6.35,89.46 ; MTH2.1 9.95,85.85 ; MTH2.1 2.74,85.85 ; MTH2.1 6.35,82.25 ; 89.59,77.81 J11.SH2 ; J11.SH2 90.95,79.17 ; J11.SH2 88.24,79.17 ; 25.13,36.4 J38.2 ; J38.2 27.34,36.4 ; J38.2 26.24,35.29 ; J38.2 26.24,37.5 ; J8.SH3 144.56,88.29 ; J8.SH3 143.46,86.58 ; J8.SH3 144.56,84.87 ; J8.SH3 145.67,86.58 ; J8.SH4 131.17,86.58 ; J8.SH4 130.07,88.29 ; J8.SH4 128.96,86.58 ; J8.SH4 130.07,84.87 ; J4.8 55.01,79.65 ; J4.8 56.04,78.62 ; J4.8 55.01,77.59 ; J4.8 53.98,78.62 ; 37.1,81.65 J47.B1 35.93,82.81 ; 3.1,53.68 J37.10 ; J37.10 3.1,55.89 ; J37.10 4.2,54.78 ; J37.10 1.99,54.78 ; J38.10 16.08,37.5 ; J38.10 17.18,36.4 ; J38.10 16.08,35.29 ; J38.10 14.97,36.4 ; M1.1 55.37,15.61 ; M1.1 51.92,13.46 ; M1.1 56.84,15.45 ; M1.1 58.82,13.46 ; 149.9,25.39 TP9.1 ; TP9.1 151.28,26.77 ; TP9.1 151.28,24.01 ; TP9.1 152.66,25.39 ; 20.05,36.4 J38.6 ; J38.6 21.16,35.29 ; J38.6 21.16,37.5 ; J38.6 22.26,36.4 ; J38.4 23.7,37.5 ; J38.4 24.8,36.4 ; J38.4 22.59,36.4 ; J38.4 23.7,35.29 ; 7.45,16.03 MTH4.1 ; MTH4.1 11.05,12.43 ; MTH4.1 14.66,16.03 ; MTH4.1 11.05,19.64 ; J4.4 55.01,76.95 ; J4.4 56.04,75.92 ; J4.4 55.01,74.89 ; J4.4 53.98,75.92 ; J49.2 101.99,30.07 ; J49.2 99.78,30.07 ; J49.2 100.88,31.18 ; J49.2 100.88,28.97 ; 150.75,82.21 MTH3.1 147.15,85.82 ; 121.83,82.23 J1.B12 121.93,81.65 ; 42.46,82.98 J47.B12 42.7,82.81 ; 150.75,12.43 MTH1.1 ; MTH1.1 147.15,16.03 ; MTH1.1 150.75,19.64 ; TP4.1 9.65,60.21 ; TP4.1 8.27,58.83 ; TP4.1 11.03,58.83 ; TP4.1 9.65,57.45 ; MTH5.1 69.76,57.52 ; MTH5.1 73.37,53.92 ; MTH5.1 66.16,53.92 ; MTH5.1 69.76,50.31 ; 14.08,80.38 J48.3 ; J48.3 12.98,82.64 ; J48.3 15.19,82.64 ; J48.3 14.08,84.9 ; J8.SH2 131.17,80.62 ; J8.SH2 128.96,80.62 ; J8.SH2 130.07,82.63 ; J8.SH2 130.07,78.61 ; 144.56,78.61 J8.SH1 ; J8.SH1 143.46,80.62 ; J8.SH1 145.67,80.62 ; J8.SH1 144.56,82.63 ; 91.26,8.54 TP7.1 ; TP7.1 92.64,9.92 ; TP7.1 94.02,8.54 ; TP7.1 92.64,7.16 ; 74.24,77.59 J3.8 ; J3.8 73.21,78.62 ; J3.8 74.24,79.65 ; J3.8 75.27,78.62 ; 90.79,80.03 J11.SH4 89.54,83.16 ; 52.25,70.21 TP5.1 53.63,71.59
  L03_PWR w0.508: 116.13,73.38 116.15,73.4
  L03_PWR w1.27: 52.07,15.3 M1.1 59.56,16.19
  L04 w0.381: 8.27,58.83 TP4.1 ; TP4.1 9.65,60.21 ; TP4.1 11.03,58.83 ; TP4.1 9.65,57.45 ; J49.2 101.99,30.07 ; J49.2 100.88,31.18 ; J49.2 99.78,30.07 ; J49.2 100.88,28.97 ; 147.15,85.82 MTH3.1 150.75,82.21 ; 130.07,78.61 J8.SH2 ; J8.SH2 131.17,80.62 ; J8.SH2 128.96,80.62 ; J8.SH2 130.07,82.63 ; 149.9,25.39 TP9.1 ; TP9.1 151.28,26.77 ; TP9.1 151.28,24.01 ; TP9.1 152.66,25.39 ; J38.6 21.16,37.5 ; J38.6 20.05,36.4 ; J38.6 21.16,35.29 ; J38.6 22.26,36.4 ; J8.SH3 145.67,86.58 ; J8.SH3 144.56,84.87 ; J8.SH3 144.56,88.29 ; J8.SH3 143.46,86.58 ; 23.7,35.29 J38.4 ; J38.4 23.7,37.5 ; J38.4 22.59,36.4 ; J38.4 24.8,36.4 ; 122.86,82.98 J1.B12 123.09,82.81 ; TP7.1 92.64,9.92 ; TP7.1 92.64,7.16 ; TP7.1 94.02,8.54 ; TP7.1 91.26,8.54 ; 85.09,63.44 TP8.1 ; TP8.1 85.09,66.2 ; TP8.1 83.71,64.82 ; TP8.1 86.47,64.82 ; 144.56,78.61 J8.SH1 ; J8.SH1 143.46,80.62 ; J8.SH1 144.56,82.63 ; J8.SH1 145.67,80.62 ; 11.05,12.43 MTH4.1 ; MTH4.1 7.45,16.03 ; MTH4.1 14.66,16.03 ; MTH4.1 11.05,19.64 ; 18.62,35.29 J38.8 ; J38.8 17.51,36.4 ; J38.8 19.72,36.4 ; J38.8 18.62,37.5 ; J9.1 152.91,70.93 ; J9.1 151.65,72.19 ; J9.1 151.65,69.68 ; J9.1 150.4,70.93 ; MTH2.1 9.95,85.85 ; MTH2.1 2.74,85.85 ; MTH2.1 6.35,89.46 ; MTH2.1 6.35,82.25 ; 3.1,53.68 J37.10 ; J37.10 3.1,55.89 ; J37.10 1.99,54.78 ; J37.10 4.2,54.78 ; 117.49,81.65 J1.B1 116.33,82.81 ; v1(51.26,12.55) 54.82,12.55 M1.1 ; 14.08,80.38 J48.3 ; J48.3 12.98,82.64 ; J48.3 14.08,84.9 ; J48.3 15.19,82.64 ; 69.76,50.31 MTH5.1 ; MTH5.1 73.37,53.92 ; MTH5.1 66.16,53.92 ; MTH5.1 69.76,57.52 ; 26.24,35.29 J38.2 ; J38.2 27.34,36.4 ; J38.2 25.13,36.4 ; J38.2 26.24,37.5 ; J4.4 56.04,75.92 ; J4.4 53.98,75.92 ; J4.4 55.01,74.89 ; 52.25,70.21 TP5.1 ; TP5.1 53.63,71.59 ; TP5.1 55.01,70.21 ; TP5.1 53.63,68.83 ; 74.24,74.89 J3.4 ; J3.4 73.21,75.92 ; J3.4 75.27,75.92 ; 53.91,15.45 M1.1 ; M1.1 55.11,12 52.4,14.71 ; M1.1 58.82,13.46 ; M1.1 56.84,15.45 ; M1.1 58.02,14.65 ; TP6.1 3.16,18.71 ; TP6.1 3.16,15.95 ; TP6.1 4.54,17.33 ; TP6.1 1.78,17.33 ; 14.97,36.4 J38.10 ; J38.10 16.08,35.29 ; J38.10 17.18,36.4 ; J38.10 16.08,37.5 ; J8.SH4 131.17,86.58 ; J8.SH4 130.07,88.29 ; J8.SH4 130.07,84.87 ; J8.SH4 128.96,86.58 ; J48.2 18.88,86.99 ; J48.2 21.14,85.89 ; J48.2 18.88,84.78 ; J48.2 16.63,85.89 ; 147.15,16.03 MTH1.1 ; MTH1.1 150.75,12.43 ; MTH1.1 150.75,19.64
  L04 w0.508: M1.1 55.37,16.23
  L05 w0.381: 100.92,82.22 J11.SH3 ; J11.SH3 103.16,79.98 ; J11.SH3 103.16,84.46 ; MTH4.1 14.66,16.03 ; MTH4.1 11.05,12.43 ; MTH4.1 7.45,16.03 ; MTH4.1 11.05,19.64 ; 41.43,82.23 J47.B12 41.53,81.65 ; 128.96,80.62 J8.SH2 ; J8.SH2 130.07,82.63 ; J8.SH2 131.17,80.62 ; J8.SH2 130.07,78.61 ; J11.SH2 90.95,79.17 ; J11.SH2 89.59,77.81 ; J11.SH2 88.24,79.17 ; J3.4 74.24,76.95 ; J3.4 75.27,75.92 ; J3.4 74.24,74.89 ; J3.4 73.21,75.92 ; 21.16,35.29 J38.6 ; J38.6 20.05,36.4 ; J38.6 21.16,37.5 ; J38.6 22.26,36.4 ; J11.SH4 91.73,84.46 ; J11.SH4 91.73,79.98 ; J11.SH4 93.96,82.22 ; J48.2 21.14,85.89 ; J48.2 18.88,84.78 ; J48.2 18.88,86.99 ; J48.2 16.63,85.89 ; J38.8 18.62,37.5 ; J38.8 17.51,36.4 ; J38.8 19.72,36.4 ; J38.8 18.62,35.29 ; 144.56,84.87 J8.SH3 ; J8.SH3 143.46,86.58 ; J8.SH3 144.56,88.29 ; J8.SH3 145.67,86.58 ; 55.01,74.89 J4.4 ; J4.4 55.01,76.95 ; J4.4 53.98,75.92 ; J4.4 56.04,75.92 ; 105.29,77.81 J11.SH1 ; J11.SH1 103.94,79.17 ; J11.SH1 106.65,79.17 ; 37.19,82.23 J47.B1 35.93,82.81 ; 74.24,77.59 J3.8 ; J3.8 74.24,79.65 ; J3.8 75.27,78.62 ; J3.8 73.21,78.62 ; 22.59,36.4 J38.4 ; J38.4 23.7,37.5 ; J38.4 24.8,36.4 ; J38.4 23.7,35.29 ; J38.2 26.24,37.5 ; J38.2 27.34,36.4 ; J38.2 26.24,35.29 ; J38.2 25.13,36.4 ; MTH2.1 9.95,85.85 ; MTH2.1 2.74,85.85 ; MTH2.1 6.35,89.46 ; MTH2.1 6.35,82.25 ; J4.8 56.04,78.62 ; J4.8 55.01,77.59 ; J4.8 55.01,79.65 ; J4.8 53.98,78.62 ; J38.10 17.18,36.4 ; J38.10 14.97,36.4 ; J38.10 16.08,35.29 ; J38.10 16.08,37.5 ; 69.76,50.31 MTH5.1 ; MTH5.1 73.37,53.92 ; MTH5.1 66.16,53.92 ; MTH5.1 69.76,57.52 ; 100.88,28.97 J49.2 ; J49.2 100.88,31.18 ; J49.2 101.99,30.07 ; J49.2 99.78,30.07 ; 85.09,63.44 TP8.1 ; TP8.1 85.09,66.2 ; TP8.1 83.71,64.82 ; TP8.1 86.47,64.82 ; 130.07,84.87 J8.SH4 ; J8.SH4 128.96,86.58 ; J8.SH4 130.07,88.29 ; J8.SH4 131.17,86.58 ; J48.3 14.08,84.9 ; J48.3 15.19,82.64 ; J48.3 14.08,80.38 ; J48.3 12.98,82.64 ; TP7.1 94.02,8.54 ; TP7.1 92.64,9.92 ; TP7.1 92.64,7.16 ; TP7.1 91.26,8.54 ; 147.15,16.03 MTH1.1 ; MTH1.1 150.75,19.64 ; MTH1.1 150.75,12.43 ; J37.10 4.2,54.78 ; J37.10 3.1,53.68 ; J37.10 3.1,55.89 ; J37.10 1.99,54.78 ; J8.SH1 144.56,82.63 ; J8.SH1 143.46,80.62 ; J8.SH1 145.67,80.62 ; J8.SH1 144.56,78.61 ; TP4.1 11.03,58.83 ; TP4.1 9.65,60.21 ; TP4.1 9.65,57.45 ; TP4.1 8.27,58.83 ; M1.1 58.82,13.46 ; M1.1 51.92,13.46 ; M1.1 56.84,15.45 ; M1.1 52.72,14.65 ; J9.1 152.91,70.93 ; J9.1 151.65,69.68 ; J9.1 150.4,70.93 ; J9.1 151.65,72.19 ; 147.15,85.82 MTH3.1 150.75,82.21 ; TP6.1 3.16,18.71 ; TP6.1 3.16,15.95 ; TP6.1 1.78,17.33 ; TP6.1 4.54,17.33 ; TP9.1 151.28,26.77 ; TP9.1 149.9,25.39 ; TP9.1 152.66,25.39 ; TP9.1 151.28,24.01 ; TP5.1 55.01,70.21 ; TP5.1 52.25,70.21 ; TP5.1 53.63,71.59 ; TP5.1 53.63,68.83 ; 117.59,82.23 J1.B1 116.33,82.81 ; 121.83,82.23 J1.B12 121.93,81.65
  L05 w1.27: 51.69,15.62 55.31,12 M1.1 55.37,12.06 59.18,15.88
  BOTTOM w0.178: 58.06,64.78 58.15,64.69 C15.2 58.15,63.82 ; U18.3 v1(70.51,13.27)
  BOTTOM w0.254: 64.78,68.98 C12.2 ; C12.2 65.84,68.98 ; C12.2 65.31,69.53 ; C3.2 87.57,70.38 ; C3.2 87.01,69.85 ; C3.2 87.01,70.91 ; 61.47,67.45 C11.2 61.47,68.51 ; U33.7 43.13,46 ; U33.5 43.05,47 43.18,46.87 ; 87.01,66.42 C6.2 ; C6.2 87.01,67.48 ; C6.2 87.57,66.95 ; 70.94,13.79 U18.3 70.08,13.79 ; v1(72.67,62.18) 72.64,62.15 U1.5 72.64,59.9 ; U33.6 43.05,46.5 43.21,46.66 ; v1(74.66,66.48) 74.64,66.48 74.63,66.47 74.64,66.46 U1.10 74.64,64.31 ; R44.1 v1(5.84,24.97) ; R45.1 v1(5.79,29.44) ; R52.1 v1(5.84,39.17)
  BOTTOM w0.305: 42.46,47.9 U33.4 43.16,47.5 ; U16.3 27.16,84.68 v1(27.41,84.43) ; C159.2 v1(47.68,82.35) ; v1(27.41,82.4) 27.16,82.15 U16.16 ; U16.17 26.66,82.13 v1(26.39,82.4) ; U33.16 v1(38.67,45) ; v1(28.42,82.4) 28.65,82.17 28.65,81.87 28.66,81.86 U16.13 ; C158.2 v1(47.65,81) ; U33.19 v1(36.82,46.5)
  BOTTOM w0.381: 92.64,7.16 TP7.1 ; TP7.1 94.02,8.54 ; TP7.1 91.26,8.54 ; TP7.1 92.64,9.92 ; MTH2.1 6.35,89.46 ; MTH2.1 6.35,82.25 ; MTH2.1 2.74,85.85 ; MTH2.1 9.95,85.85 ; C11.2 v1(60.82,67.98) ; 34.35,76.07 C172.1 ; C172.1 36.21,76.07 ; C172.1 35.28,77.7 ; C172.1 35.28,74.44 ; J37.10 4.2,54.78 ; J37.10 1.99,54.78 ; J37.10 3.1,55.89 ; J37.10 3.1,53.68 ; 137.93,77.96 U4.3 ; U4.3 138.61,78.69 ; U4.3 137.25,78.69 ; 40.09,48 40.54,48.45 ; 40.09,48 40.09,47.93 ; 40.09,48 39.65,48.44 ; 40.09,48 40.09,48.58 ; 62.86,54.85 Y1.2 61.98,53.87 ; J17.11 130.48,1.8 ; J17.11 v1(128.32,1.8) ; J17.11 129.53,2.98 ; 40.09,47.93 40.55,47.93 ; 40.09,47.93 39.62,47.93 ; 40.09,47.93 U33.2 ; 85.27,66.24 85.27,65 TP8.1 ; J38.6 21.16,37.5 ; J38.6 21.16,35.29 ; J38.6 20.05,36.4 ; J38.6 22.26,36.4 ; 29.29,78.87 C60.2 28.52,78.33 ; 42.85,53.34 C192.2 ; C192.2 43.63,54.32 ; C192.2 44.41,53.34 ; C192.2 43.63,52.36 ; 129.27,13.51 J17.13 ; J17.13 130.48,13.51 ; J17.13 v1(129.88,11.64) ; C34.2 19.37,25.13 ; C34.2 19.37,23.27 ; C34.2 18.19,24.2 ; C34.2 20.55,24.2 ; v1(70.61,62.61) 70.37,62.37 R10.2 ; v1(60.85,71.45) U39.3 ; 60.28,56.07 Y1.4 ; Y1.4 60.28,58.03 ; Y1.4 59.4,57.05 ; M1.1 55.37,15.61 ; M1.1 56.84,15.45 ; M1.1 58.82,13.46 ; M1.1 52.72,14.65 ; v1(34.16,49.53) 34.6,49.53 34.98,49.15 R403.2 ; 87.01,67.57 C5.2 87.57,68.1 ; J17.16 116.23,2.58 ; J17.16 v1(117.55,1.55) ; J17.16 115.37,1.55 ; C35.2 34.8,25.15 v1(34.24,24.59) ; Q14.S v1(48.22,72.35) ; Q14.S 47.13,71.72 ; Q14.S 46.55,72.35 ; Q14.S 47.13,72.98 ; J11.SH3 103.16,84.46 ; J11.SH3 103.16,79.98 ; J11.SH3 100.92,82.22 ; 55.01,77.59 J4.8 ; J4.8 55.01,79.65 ; J4.8 56.04,78.62 ; 134.98,79.07 C17.2 ; C17.2 136.04,79.07 ; C17.2 135.51,78.52 ; C29.2 28.09,32.34 ; C29.2 27.31,31.36 ; C29.2 28.09,30.38 ; 74.24,74.89 J3.4 74.24,76.95 ; 30.44,85.95 30.72,86.23 R372.1 30.12,86.72 ; J48.2 18.88,86.99 ; J48.2 16.63,85.89 ; J48.2 21.14,85.89 ; J48.2 18.88,84.78 ; C15.2 57.32,64.25 v1(57.3,64.24) ; 17.51,36.4 J38.8 ; J38.8 19.72,36.4 ; J38.8 18.62,37.5 ; J38.8 18.62,35.29 ; MTH4.1 11.05,19.64 ; MTH4.1 14.66,16.03 ; MTH4.1 11.05,12.43 ; MTH4.1 7.45,16.03 ; D31.A 16.32,69.8 ; D31.A 13.26,69.8 ; D31.A 14.79,68.47 ; D31.A 14.79,71.13 ; MTH1.1 150.75,19.64 ; MTH1.1 147.15,16.03 ; MTH1.1 150.75,12.43 ; R3.1 60.66,58.36 v1(60.68,58.34) ; 15.99,65.23 R394.1 ; R394.1 16.54,64.7 ; R394.1 16.54,65.76 ; v1(70.08,66.36) R7.2 ; J38.4 24.8,36.4 ; J38.4 22.59,36.4 ; J38.4 23.7,35.29 ; J38.4 23.7,37.5 ; J17.14 116.58,15.45 ; J17.14 115.37,15.45 ; J17.14 v1(115.98,16.64) ; 30.93,65.32 C228.N ; C228.N 30.93,67.48 ; C228.N 28.9,66.4 ; C216.2 37.24,52.7 ; C216.2 36.46,53.68 ; C216.2 35.68,52.7 ; J46.1 v1(80.28,2.3) ; J46.1 76.2,2.3 ; J46.1 77.88,0.92 ; 151.28,24.01 TP9.1 ; TP9.1 151.28,26.77 ; TP9.1 152.66,25.39 ; TP9.1 149.9,25.39 ; 59.09,59.08 C16.2 59.62,58.52 ; J17.15 v1(115.95,10.77) ; 3.16,15.95 TP6.1 ; TP6.1 4.54,17.33 ; TP6.1 1.78,17.33 ; TP6.1 3.16,18.71 ; D30.A 16.47,74.32 ; D30.A 13.21,74.32 ; D30.A 14.84,73.24 ; D30.A 14.84,75.4 ; 143.46,86.58 J8.SH3 ; J8.SH3 144.56,88.29 ; J8.SH3 145.67,86.58 ; J48.3 15.19,82.64 ; J48.3 14.08,80.38 ; J48.3 12.98,82.64 ; J48.3 14.08,84.9 ; C191.2 43.63,52.16 ; C191.2 43.63,50.2 ; C191.2 44.41,51.18 ; C191.2 42.85,51.18 ; 87.01,69.72 C4.2 87.57,69.19 ; v1(35.51,22.94) 35.53,22.92 R64.2 ; 28.09,28.27 C28.2 ; C28.2 28.09,30.23 ; C28.2 27.31,29.25 ; C31.2 23.66,23.81 ; 80.77,70.01 R4.2 80.24,69.45 ; R6.2 70.51,63.25 v1(70.61,63.35) ; TP4.1 9.65,60.21 ; TP4.1 11.03,58.83 ; TP4.1 9.65,57.45 ; TP4.1 8.27,58.83 ; TP5.1 55.01,70.21 ; TP5.1 53.63,71.59 ; TP5.1 52.25,70.21 ; TP5.1 53.63,68.83 ; C227.N 31.67,58.87 ; C227.N 31.67,56.7 ; C227.N 29.64,57.78 ; 103.94,79.17 J11.SH1 ; J11.SH1 106.65,79.17 ; J11.SH1 105.29,77.81 ; 55.01,76.95 J4.4 55.01,74.89 ; C36.2 31.09,18.67 C229.2 30.88,19.83 U12.7 ; 15.99,60.78 R393.1 ; R393.1 16.54,60.25 ; R393.1 16.54,61.31 ; TP8.1 86.47,64.82 ; TP8.1 85.09,63.44 ; TP8.1 85.09,64.95 84.12,65.91 ; 147.15,85.82 MTH3.1 150.75,82.21 ; 30.49,88.39 30.72,88.16 C180.1 30.19,87.73 ; C56.2 v1(70.76,18.16) ; 100.88,28.97 J49.2 ; J49.2 99.78,30.07 ; J49.2 100.88,31.18 ; J49.2 101.99,30.07 ; C185.N 48.65,59.09 ; C185.N 50.68,58.01 ; C185.N 48.65,56.93 ; U15.5 v1(84.57,56.35) ; 25.21,23.15 C30.2 24.68,23.71 ; J17.12 v1(129.88,6.74) ; J17.12 129.88,9.78 ; J17.12 130.48,8.43 ; J11.SH4 91.73,84.46 ; J11.SH4 93.96,82.22 ; J11.SH4 91.73,79.98 ; J38.2 27.34,36.4 ; J38.2 26.24,37.5 ; J38.2 26.24,35.29 ; J38.2 25.13,36.4 ; 37.19,82.23 J47.B1 35.93,82.81 ; v1(56.67,71.53) 56.68,71.54 U38.3 ; 33.55,23.65 U12.9 29.48,23.65 ; R2.2 76.87,58.66 v1(76.86,58.65) ; C14.2 R8.2 68.1,59 v1(68.17,59.08) ; J17.6 v1(126.46,2.71) ; J8.SH4 131.17,86.58 ; J8.SH4 128.96,86.58 ; J8.SH4 130.07,88.29 ; 30.94,80.82 C61.2 v1(30.26,81.31) ; C62.2 31.07,80.29 30.68,80.29 30.38,80.59 v1(30.28,80.59) ; 68.65,59.87 C10.2 68.12,60.43 ; 139.69,79.83 C18.2 140.22,79.28 ; 84.03,68.95 C2.2 ; C2.2 85.21,69.88 ; C2.2 84.03,70.81 ; C2.2 82.85,69.88 ; v1(29.31,79.88) C59.2 28.52,80.43 ; U33.2 39.65,46.9 ; U33.2 40.52,46.9 ; C7.2 61.91,58.79 v1(61.57,58.45) ; 74.24,77.59 J3.8 ; J3.8 74.24,79.65 ; J3.8 75.27,78.62 ; 69.76,50.31 MTH5.1 ; MTH5.1 69.76,57.52 ; MTH5.1 73.37,53.92 ; MTH5.1 66.16,53.92 ; 42.83,48.87 C195.2 ; C195.2 43.38,49.4 ; C195.2 42.83,49.93 ; 36.46,49.82 C215.2 ; C215.2 37.24,50.8 ; C215.2 35.68,50.8 ; C225.1 v1(33.12,44.83) ; R85.2 v1(74.47,16.1) ; C214.2 37.32,49.83 ; C214.2 36.76,49.3 ; C214.2 37.32,48.77 ; U36.3 78.78,74.01 v1(78.77,74.02) ; J38.10 16.08,37.5 ; J38.10 17.18,36.4 ; J38.10 14.97,36.4 ; J38.10 16.08,35.29 ; R384.1 43.92,46.51 v1(43.71,46.71) ; 121.93,81.65 J1.B12 121.83,82.23 ; v1(48.11,73.08) 47.55,73.63 R374.1 ; 69.8,64.66 C13.2 70.36,64.13 ; 117.59,82.23 J1.B1 117.49,81.65 ; U15.2 84.57,59.91 v1(84.89,60.22) ; 69.51,59.87 C9.2 70.04,60.43 ; 80.82,62.72 C1.2 80.82,63.78 ; C32.2 22.65,23.84 ; v1(30.28,79.88) 30.28,79.43 30.51,79.2 C63.2 31.15,78.62 ; C224.1 v1(33.1,43.31) ; U37.3 v1(75.54,74.17) ; 21.1,23.15 C33.2 21.63,23.71 ; C55.2 v1(74.5,17.14) ; 90.95,79.17 J11.SH2 89.59,77.81 ; R84.2 v1(70.71,17.12)
  BOTTOM w0.508: U2.2 v1(80.73,65.69) ; C51.2 v1(85.08,62.21) 85.09,62.2 ; v1(80.26,59.74) 80.28,59.76 C52.1 ; U9.2 v1(129.31,18.08) ; C8.2 v1(64.52,58.62) ; C1.2 v1(80.02,63.25)
  BOTTOM w0.635: U12.9 30.88,23.01 U12.7
  BOTTOM w1.27: 58.42,14.99 55.43,12 M1.1 55.31,12 51.56,15.75
  vias: v1(1.04,84.76) v1(1.04,82.63) v1(1.04,80.09) v1(1.04,77.55) v1(1.04,75.01) v1(1.04,72.47) v1(1.04,69.93) v1(1.04,67.39) v1(1.04,64.85) v1(1.04,62.31) v1(1.04,59.77) v1(1.04,47.9) v1(0.99,25.98) v1(0.99,23.88) v1(1.02,21.13) v1(1.02,13.11) v1(1.07,57.43) v1(1.07,54.89) v1(1.07,52.35) v1(1.07,49.81) v1(1.07,44.73) v1(1.07,43) v1(1.07,40.06) v1(1.07,38.02) v1(1.09,35.48) v1(1.12,33.83) v1(1.07,31.09) v1(1.07,29.49) v1(1.07,18.54) v1(1.07,16.03) v1(1.09,10.13) v1(2.31,49.15) v1(2.31,47.88) v1(3.58,49.15) v1(3.58,47.88) v1(3.91,79.55) v1(4.04,14.17) v1(4.67,39.75) v1(4.72,33.96) v1(4.72,31.19) v1(4.95,25.48) v1(5.18,79.55) v1(5.18,78.28) v1(5.18,42.42) v1(5.97,75.84) v1(5.99,70.16) v1(6.02,63.6) v1(6.05,61.98) v1(6.02,16.48) v1(6.07,65.63) v1(6.12,26.34) v1(6.32,53.57) v1(6.63,48.29) v1(6.63,47.02) v1(6.58,19.2) v1(6.86,58.98) v1(6.99,71.91) v1(7.04,25.35) v1(7.09,42.6) v1(7.09,12.47) v1(7.34,65.63) v1(7.34,64.36) v1(7.75,67.67) v1(7.72,39.88) v1(7.75,31.22) v1(7.67,24.08) v1(7.9,48.29) v1(7.9,47.02) v1(8.03,51.97) v1(8.03,45.44) v1(8.1,34.01) v1(8.43,79.5) v1(8.43,78.23) v1(8.38,75.08) v1(8.38,73.81) v1(8.48,26.09) v1(8.71,61.37) v1(8.76,63.88) v1(9.07,56.03) v1(9.07,54.76) v1(9.42,65.53) v1(9.42,24.23) v1(9.53,72.75) v1(9.7,79.5) v1(9.7,78.23) v1(9.65,75.08) v1(9.65,73.81) v1(9.75,70.97) v1(9.83,50.01) v1(9.86,62.38) v1(10.34,56.03) v1(10.34,54.76) v1(10.57,63.83) v1(10.72,68.33) v1(11.07,61.26) v1(11.2,1.07) v1(11.43,10.31) v1(11.73,67.08) v1(11.68,25.6) v1(11.79,72.69) v1(11.96,83.29) v1(12.04,62.36) v1(12.14,70.64) v1(12.12,69.37) v1(12.29,85.98) v1(12.37,88.42) v1(12.4,75.51) v1(12.5,74.09) v1(12.93,25.91) v1(13.41,68.17) v1(13.39,66.19) v1(13.64,64.52) v1(13.74,1.07) v1(13.92,76.61) v1(14,23.65) v1(14.07,72.9) v1(14.07,71.91) v1(14.15,25.3) v1(14.35,8.81) v1(14.35,6.27) v1(14.35,3.73) v1(14.48,86.51) v1(14.45,11.84) v1(14.63,19.81) v1(14.99,22.43) v1(15.14,88.6) v1(15.42,72.95) v1(15.42,71.86) v1(15.37,65.23) v1(15.39,24.31) v1(15.6,76.58) v1(15.62,25.76) v1(16.03,66.22) v1(16.03,40.79) v1(16.13,43.43) v1(16.23,50.75) v1(16.23,49.48) v1(16.28,1.07) v1(16.43,23.55) v1(16.51,61.87) v1(16.61,86.66) v1(16.56,59.66) v1(16.89,8.81) v1(16.89,6.27) v1(16.89,3.73) v1(17.27,34.67) v1(17.27,32.13) v1(17.27,29.59) v1(17.35,25.35) v1(17.35,24.33) v1(17.5,50.75) v1(17.5,49.48) v1(17.73,88.44) v1(18.01,12.22) v1(18.49,25.86) v1(18.82,1.07) v1(18.9,43.18) v1(19.43,54.41) v1(19.43,8.81) v1(19.43,6.27) v1(19.43,3.73) v1(19.63,56.77) v1(19.81,34.67) v1(19.81,32.13) v1(19.81,29.59) v1(19.89,25.86) v1(20.27,50.42) v1(20.27,49.15) v1(21.29,25.48) v1(21.29,24.33) v1(21.36,1.07) v1(21.54,50.42) v1(21.54,49.15) v1(21.84,43.15) v1(22.17,24.33) v1(22.35,34.67) v1(22.35,32.13) v1(22.35,29.59) v1(23.19,24.33) v1(23.34,8.79) v1(23.34,6.25) v1(23.34,3.71) v1(23.8,59.16) v1(23.85,43.36) v1(23.9,1.07) v1(24.21,24.33) v1(24.71,86.18) v1(24.89,34.67) v1(24.89,32.13) v1(24.89,29.59) v1(25.32,53.85) v1(25.35,24.33) v1(25.73,23.19) v1(25.81,79.68) v1(25.88,8.79) v1(25.88,6.25) v1(25.88,3.71) v1(26.24,43.13) v1(26.39,84.43) v1(26.39,83.41) v1(26.44,1.07) v1(26.87,32.59) v1(26.87,31.32) v1(26.87,30.3) v1(26.87,29.29) v1(26.87,28.14) v1(27.13,24.33) v1(27.13,22.94) v1(27.41,83.41) v1(28.04,32.82) v1(28.27,28.02) v1(28.42,84.43) v1(28.42,83.41) v1(28.42,8.79) v1(28.42,6.25) v1(28.42,3.71) v1(28.52,24.33) v1(28.52,22.94) v1(28.98,1.07) v1(29.31,59.11) v1(29.31,56.64) v1(29.36,64.92) v1(29.36,63.88) v1(29.84,87.27) v1(29.92,88.37) v1(29.87,86.13) v1(29.9,50.06) v1(30.25,24.28) v1(30.25,23.01) v1(30.56,83.67) v1(30.63,49.23) v1(30.73,59.44) v1(30.71,56.19) v1(30.91,67.77) v1(30.89,64.87) v1(31.52,24.28) v1(31.52,23.01) v1(31.52,1.07) v1(32.23,83.59) v1(32.28,64.9) v1(32.36,67.77) v1(32.46,56.16) v1(32.56,59.44) v1(32.79,80.67) v1(32.79,24.28) v1(32.79,23.01) v1(33.35,82.93) v1(33.68,79.6) v1(33.73,30.1) v1(33.86,41.28) v1(33.91,36.93) v1(33.99,81.28) v1(33.99,73.25) v1(33.99,38.51) v1(34.06,1.07) v1(34.24,23.06) v1(34.65,28.7) v1(34.7,80.64) v1(35.23,79.12) v1(35.33,50.7) v1(35.38,53.65) v1(35.36,52.68) v1(35.36,51.69) v1(35.84,80.57) v1(35.84,71.02) v1(35.76,24.08) v1(36.47,28.58) v1(36.55,49.58) v1(36.65,21.92) v1(36.93,70.94) v1(36.91,25.22) v1(36.91,1.04) v1(37.14,34.34) v1(37.26,79.32) v1(37.39,2.87) v1(37.47,10.54) v1(37.47,7.9) v1(37.49,5.26) v1(38.25,79.78) v1(40.09,48.8) v1(40.21,28.65) v1(40.18,21.13) v1(40.23,16) v1(40.18,12.4) v1(40.28,18.69) v1(40.41,71.55) v1(40.46,79.6) v1(40.94,23.55) v1(41.43,73.58) v1(41.43,72.57) v1(41.43,71.55) v1(41.5,22.15) v1(41.55,24.84) v1(42.16,12.67) v1(42.27,19.46) v1(42.44,73.58) v1(42.44,72.57) v1(42.44,71.55) v1(42.37,15.27) v1(42.75,48.11) v1(42.7,17.5) v1(43.21,34.16) v1(43.23,20.52) v1(43.38,47.37) v1(43.54,48.13) v1(43.54,25.09) v1(43.48,22.4) v1(43.61,49.43) v1(44.09,12.55) v1(44.32,80.65) v1(44.32,49.86) v1(44.27,47.78) v1(44.35,19.3) v1(44.4,14.17) v1(44.48,46.91) v1(44.45,16.87) v1(44.81,53.92) v1(44.81,52.93) v1(44.81,51.84) v1(44.78,50.67) v1(44.88,48.49) v1(45.11,22.1) v1(45.62,50.24) v1(46.28,48.92) v1(46.25,34.52) v1(46.33,15.8) v1(46.53,21.89) v1(46.61,35.76) v1(46.58,24.59) v1(46.94,51.64) v1(47.14,20.32) v1(47.32,50.14) v1(47.55,12.6) v1(47.66,39.23) v1(47.83,53.54) v1(47.8,35.15) v1(47.85,54.31) v1(47.88,52.81) v1(48.26,51.08) v1(48.46,22.1) v1(48.62,59.77) v1(48.62,56.21) v1(48.56,44.25) v1(48.69,54.46) v1(48.67,40.94) v1(48.82,88.21) v1(48.82,85.67) v1(48.82,24.54) v1(48.9,51.79) v1(49.1,68.22) v1(49.07,49.89) v1(49.23,52.91) v1(49.17,43.38) v1(49.28,50.55) v1(49.28,18.49) v1(49.63,40.94) v1(49.68,72.09) v1(49.73,69.39) v1(49.68,59.77) v1(49.73,56.41) v1(49.68,55.42) v1(49.73,15.6) v1(49.78,44.25) v1(49.94,51.51) v1(50.23,65.86) v1(50.49,52.93) v1(50.6,54.31) v1(50.6,43.33) v1(50.66,67.87) v1(50.8,24.79) v1(50.95,70.15) v1(51,20.17) v1(51.13,58.32) v1(51.1,40.94) v1(51.26,52.02) v1(51.26,50.75) v1(51.36,88.21) v1(51.36,85.67) v1(51.49,65.64) v1(51.64,56.11) v1(51.76,53.54) v1(52.04,60.45) v1(52.07,39.22) v1(52.17,72.03) v1(52.22,43.33) v1(52.39,66.95) v1(52.43,40.89) v1(52.54,50.4) v1(52.53,22.1) v1(52.63,18.49) v1(52.7,49.4) v1(52.93,46.63) v1(52.88,36.78) v1(53.24,52.5) v1(53.26,39.18) v1(53.52,55.75) v1(53.49,45.97) v1(53.67,49.07) v1(53.85,25.15) v1(53.9,88.21) v1(53.9,85.67) v1(53.87,65.46) v1(54,73.63) v1(54.05,51.31) v1(54.1,46.75) v1(54.05,16.66) v1(54.15,58.47) v1(54.31,72.09) v1(54.33,61.57) v1(54.43,62.33) v1(54.48,56.85) v1(54.46,53.49) v1(54.71,67.79) v1(54.71,65.99) v1(54.71,64.8) v1(54.69,63.86) v1(54.66,44.3) v1(54.76,40.89) v1(54.97,20.32) v1(55.07,60.15) v1(55.12,59.03) v1(55.12,54.41) v1(55.22,73.81) v1(55.22,68.81) v1(55.22,57.66) v1(55.32,70.66) v1(55.3,61.26) v1(55.3,55.6) v1(55.47,82.96) v1(55.5,72.92) v1(55.63,52.48) v1(55.65,71.93) v1(55.68,40.89) v1(55.83,74.19) v1(55.78,51.41) v1(55.78,49.89) v1(55.83,25.4) v1(56.01,70.16) v1(56.03,66.4) v1(56.03,65.25) v1(55.98,22.15) v1(56.08,63.86) v1(56.08,54) v1(56.19,58.75) v1(56.29,68.05) v1(56.44,88.21) v1(56.44,85.67) v1(56.44,61.39) v1(56.44,56.29) v1(56.54,60.4) v1(56.57,62.43) v1(56.59,52.68) v1(56.59,39.32) v1(56.69,18.49) v1(56.85,81.08) v1(57.23,59.46) v1(57.2,50.67) v1(57.28,83.97) v1(57.3,65.84) v1(57.38,74.09) v1(57.4,55.52) v1(57.35,49.78) v1(57.4,41.05) v1(57.45,57.48) v1(57.47,31.84) v1(57.58,71.09) v1(57.71,71.88) v1(57.68,69.37) v1(57.71,53.9) v1(57.66,52.32) v1(57.76,72.97) v1(57.81,39.32) v1(58.06,74.52) v1(58.14,62.51) v1(58.09,60.3) v1(58.12,25.15) v1(58.22,50.95) v1(58.27,58.14) v1(58.32,20.07) v1(58.52,64.97) v1(58.52,61.09) v1(58.6,72.44) v1(58.6,65.79) v1(58.62,44.32) v1(58.62,30.78) v1(58.67,70.36) v1(58.67,68.43) v1(58.83,56.24) v1(58.93,73.79) v1(58.89,58.97) v1(58.88,55.47) v1(58.85,34.42) v1(58.98,88.21) v1(58.98,85.67) v1(59,57.02) v1(59.03,54.41) v1(59.13,83.11) v1(59.05,57.73) v1(59.08,53.64) v1(59.23,81.2) v1(59.16,50.93) v1(59.18,49.89) v1(59.23,33.1) v1(59.33,70.87) v1(59.31,69.11) v1(59.31,67.03) v1(59.72,74.4) v1(59.66,73.33) v1(59.66,58.35) v1(59.74,52.22) v1(59.74,39.27) v1(59.69,22.1) v1(59.79,72.47) v1(59.89,34.39) v1(59.97,30.4) v1(60.15,50.93) v1(60.12,44.32) v1(60.1,25.4) v1(60.15,18.54) v1(60.33,31.9) v1(60.55,53.64) v1(60.65,83.26) v1(60.68,80.75) v1(60.81,67.13) v1(60.86,16.66) v1(61.06,33.3) v1(61.19,47.47) v1(61.21,39.27) v1(61.34,69.75) v1(61.29,66.6) v1(61.44,67.28) v1(61.52,88.21) v1(61.52,85.67) v1(61.52,48.41) v1(61.47,30.78) v1(61.7,74.5) v1(61.82,72.44) v1(61.82,70.92) v1(61.82,53.59) v1(61.85,50.01) v1(61.98,73.48) v1(62.03,25.09) v1(62.23,51.66) v1(62.2,33.22) v1(62.28,31.8) v1(62.48,58.45) v1(62.48,47.57) v1(62.59,72.19) v1(62.6,40.85) v1(62.69,69.75) v1(62.71,20.47) v1(62.76,74.3) v1(62.81,73.53) v1(62.76,39.25) v1(62.84,22.55) v1(62.84,13.41) v1(62.91,65.34) v1(62.93,63.87) v1(62.93,62.36) v1(63.04,53.64) v1(63.25,52.63) v1(63.35,30.56) v1(63.55,71.02) v1(63.83,50.01) v1(63.8,33.53) v1(63.86,18.49) v1(64.01,53.06) v1(64.01,25.35) v1(64.06,88.21) v1(64.06,85.67) v1(64.19,72.24) v1(64.16,51.97) v1(64.41,69.75) v1(64.44,36.63) v1(64.48,65.34) v1(64.5,63.87) v1(64.49,62.36) v1(64.52,56.95) v1(64.49,31.9) v1(64.62,44.32) v1(64.72,54.51) v1(64.85,15.85) v1(65.02,47.14) v1(65.02,34.59) v1(65.1,52.91) v1(65.07,35.61) v1(65.07,21.79) v1(65.18,57.66) v1(65.33,69.75) v1(65.43,71.02) v1(65.43,30.78) v1(65.48,51.92) v1(65.53,33.53) v1(65.63,56.08) v1(65.58,48.49) v1(65.68,50.11) v1(65.74,26.57) v1(65.68,12.65) v1(65.99,63.87) v1(65.99,62.36) v1(66.35,20.14) v1(66.45,31.9) v1(66.6,88.21) v1(66.6,85.67) v1(66.62,57.48) v1(66.6,34.54) v1(66.62,17.12) v1(66.88,45.8) v1(66.9,40.06) v1(66.85,23.16) v1(67.03,72.24) v1(67.08,69.75) v1(67.11,66.55) v1(67.21,68.45) v1(67.16,26.8) v1(67.26,48.44) v1(67.26,30.89) v1(67.26,24.94) v1(67.39,71.02) v1(67.36,33.53) v1(67.51,31.95) v1(67.49,12.5) v1(67.72,47.09) v1(68.05,57.53) v1(68.25,30.33) v1(68.28,59.74) v1(68.4,69.72) v1(68.35,68.45) v1(68.53,44.91) v1(68.55,38.94) v1(68.73,45.72) v1(68.66,31.6) v1(69.04,59.69) v1(69.14,88.21) v1(69.14,85.67) v1(69.19,58.88) v1(69.32,67.87) v1(69.29,48.49) v1(69.34,22.76) v1(69.44,45.59) v1(69.52,72.24) v1(69.47,71.02) v1(69.75,69.75) v1(69.75,59.64) v1(69.88,64.82) v1(69.9,24.54) v1(69.93,12.62) v1(69.95,68.5) v1(69.98,44.83) v1(70.26,60.2) v1(70.31,41.86) v1(70.41,67.74) v1(70.59,64.08) v1(70.56,47.09) v1(70.92,26.77) v1(70.99,41.05) v1(71.12,23.16) v1(71.22,72.11) v1(71.2,70.71) v1(71.22,68.22) v1(71.25,63.73) v1(71.2,58.67) v1(71.35,42.47) v1(71.48,15.16) v1(71.68,88.21) v1(71.68,85.67) v1(71.83,48.56) v1(72.24,73.41) v1(72.21,66.42) v1(72.29,59.05) v1(72.31,34.67) v1(72.44,12.52) v1(72.49,59.74) v1(72.52,57.12) v1(72.54,26.54) v1(72.54,22.81) v1(72.75,69.29) v1(72.72,58.37) v1(72.72,40.39) v1(72.85,70.71) v1(72.92,39.12) v1(73.02,45.72) v1(73.1,47.19) v1(73.05,42.65) v1(73.2,74.04) v1(73.28,11.02) v1(73.33,8.38) v1(73.3,5.56) v1(73.28,1.3) v1(73.46,48.51) v1(73.48,23.93) v1(73.66,72.03) v1(73.81,44.58) v1(73.81,31.93) v1(73.94,73.76) v1(73.86,70.71) v1(73.89,69.19) v1(73.86,67.87) v1(73.99,54.15) v1(74.14,58.34) v1(74.12,40.87) v1(74.09,38.71) v1(74.12,0.86) v1(74.22,88.21) v1(74.22,85.67) v1(74.22,82.78) v1(74.24,57.15) v1(74.17,3.15) v1(74.35,80.7) v1(74.35,45.77) v1(74.37,50.75) v1(74.42,26.52) v1(74.52,74.24) v1(74.47,59.08) v1(74.55,49.25) v1(74.52,23.09) v1(74.63,69.62) v1(74.63,42.32) v1(75.23,39.62) v1(75.16,23.9) v1(75.31,43.64) v1(75.31,31.22) v1(75.36,66.27) v1(75.44,58.22) v1(75.39,29.13) v1(75.44,2.26) v1(75.44,1.32) v1(75.46,37.03) v1(75.46,3.25) v1(75.62,49.43) v1(75.57,48.06) v1(75.74,52.5) v1(75.92,62.71) v1(75.87,45.77) v1(76,54.25) v1(76,22.86) v1(76.07,65.56) v1(76.12,57.18) v1(76.07,51.26) v1(76.53,74.57) v1(76.53,26.54) v1(76.53,18.34) v1(76.51,16.43) v1(76.61,72.75) v1(76.58,71.88) v1(76.56,8.2) v1(76.73,53.47) v1(76.76,88.21) v1(76.76,85.67) v1(76.76,24.13) v1(76.86,51.51) v1(76.89,31.04) v1(77.01,49.43) v1(77.06,74.07) v1(77.27,56.36) v1(77.32,20.83) v1(77.55,74.55) v1(77.55,50.75) v1(77.62,71.32) v1(77.72,72.77) v1(77.67,70.61) v1(77.72,67.08) v1(77.75,66.12) v1(77.77,52.43) v1(77.83,8.2) v1(77.85,61.34) v1(77.93,55.55) v1(78,81.91) v1(78.31,26.54) v1(78.38,17.68) v1(78.69,66.45) v1(78.66,63.37) v1(79.02,31.04) v1(79.05,19.81) v1(79.07,68.02) v1(79.1,8.2) v1(79.3,88.21) v1(79.3,85.67) v1(79.4,80.42) v1(79.48,59.59) v1(79.6,74.88) v1(79.6,69.22) v1(79.83,68.07) v1(79.78,49.38) v1(79.81,46.33) v1(79.76,22.4) v1(79.91,72.64) v1(80.01,70.51) v1(80.06,74.12) v1(80.11,52.37) v1(80.06,50.7) v1(80.16,71.65) v1(80.19,47.96) v1(80.32,18.31) v1(80.26,3.28) v1(80.29,1.3) v1(80.37,26.72) v1(80.37,8.2) v1(80.57,29.97) v1(80.72,33.83) v1(80.77,70.19) v1(80.98,45.16) v1(81.13,22.15) v1(81.38,49.43) v1(81.64,46.38) v1(81.64,8.2) v1(81.69,48.06) v1(81.84,88.21) v1(81.84,85.67) v1(81.84,61.39) v1(82.02,50.72) v1(81.99,20.57) v1(81.99,0.94) v1(82.25,40.54) v1(82.19,37.39) v1(82.25,34.75) v1(82.3,44.7) v1(82.32,42.27) v1(82.35,31.09) v1(82.45,69.44) v1(82.39,21.39) v1(82.5,73.41) v1(82.51,70.38) v1(82.55,49.4) v1(82.68,53.01) v1(82.78,48.03) v1(82.91,8.2) v1(83.11,71.07) v1(83.16,46.38) v1(83.21,38.71) v1(83.26,35.64) v1(83.36,30.02) v1(83.52,49.43) v1(83.72,48.03) v1(83.67,25.3) v1(83.72,22.05) v1(84.02,68.4) v1(84.1,46.46) v1(84.33,62.92) v1(84.38,88.21) v1(84.38,85.67) v1(84.43,31.09) v1(84.35,20.65) v1(84.53,37.39) v1(84.79,27.23) v1(84.89,72.72) v1(84.94,34.29) v1(84.96,0.91) v1(85.17,68.66) v1(85.19,17.02) v1(85.47,69.8) v1(85.67,61.29) v1(85.7,47.85) v1(85.67,22.94) v1(85.7,21.46) v1(85.8,25.86) v1(85.88,50.67) v1(85.88,49.38) v1(85.85,20.35) v1(86.36,40.59) v1(86.39,19) v1(86.56,35.71) v1(86.79,55.91) v1(86.79,27.18) v1(86.79,15.11) v1(86.79,13.21) v1(87.2,65.89) v1(87.3,64.06) v1(87.3,47.85) v1(87.27,31.14) v1(87.45,24.54) v1(87.5,0.91) v1(87.55,46.28) v1(87.78,18.24) v1(87.91,69.9) v1(87.91,68.91) v1(87.94,66.88) v1(87.93,40.26) v1(87.88,34.59) v1(88.01,19.71) v1(87.99,2.41) v1(88.09,4.06) v1(88.47,17.07) v1(88.75,60.07) v1(88.67,50.7) v1(88.8,84.63) v1(88.8,49.35) v1(88.93,86.28) v1(88.9,12.04) v1(88.98,71.12) v1(88.95,23.93) v1(89.05,68.5) v1(89.1,26.16) v1(89.2,31.14) v1(89.26,2.41) v1(89.36,4.06) v1(89.59,22.1) v1(89.76,18.49) v1(89.87,16.31) v1(90.02,62.84) v1(89.97,47.88) v1(90.04,0.91) v1(90.14,11.84) v1(90.22,46.25) v1(90.32,27.13) v1(90.4,49.38) v1(90.53,2.41) v1(90.63,10.31) v1(90.63,4.06) v1(90.81,12.85) v1(91.01,74.57) v1(91.11,73.18) v1(91.34,17.12) v1(91.54,72.16) v1(91.47,18.21) v1(91.54,11.99) v1(91.59,21.89) v1(91.8,2.41) v1(91.9,10.41) v1(91.9,4.06) v1(92.25,57.66) v1(92.3,50.67) v1(92.3,27.13) v1(92.43,71.4) v1(92.35,69.39) v1(92.48,47.96) v1(92.58,22.12) v1(92.58,0.91) v1(92.76,67.21) v1(92.84,66.24) v1(93.04,44.68) v1(93.07,2.41) v1(93.19,61.19) v1(93.22,58.85) v1(93.17,4.06) v1(93.32,65.28) v1(93.29,46.25) v1(93.57,56.34) v1(93.73,64.16) v1(94.01,59.92) v1(93.98,54.53) v1(94.01,9.83) v1(94.34,2.41) v1(94.36,42.93) v1(94.44,4.06) v1(94.59,65.46) v1(94.74,63.32) v1(94.74,50.67) v1(94.84,72.01) v1(94.82,47.98) v1(94.77,40.33) v1(94.77,35.81) v1(94.89,45.92) v1(94.95,12.88) v1(95.02,66.62) v1(94.97,31.85) v1(94.97,30.61) v1(95.12,0.91) v1(95.5,65.13) v1(95.81,71.88) v1(95.76,62.36) v1(95.78,24.41) v1(95.8,17.46) v1(95.91,54.58) v1(96.04,87.02) v1(96.06,22.43) v1(96.16,64.24) v1(96.16,40.23) v1(96.27,68.02) v1(96.34,50.67) v1(96.29,44.68) v1(96.39,58.22) v1(96.39,47.93) v1(96.47,70.05) v1(96.65,59.61) v1(96.75,65.86) v1(96.85,61.19) v1(96.88,33.93) v1(96.85,31.85) v1(97,37.77) v1(97.23,63.17) v1(97.23,57.12) v1(97.23,49.4) v1(97.26,67.59) v1(97.28,66.57) v1(97.54,40.44) v1(97.56,65.02) v1(97.64,38.46) v1(97.56,17.37) v1(97.66,0.91) v1(97.87,60.15) v1(97.92,58.04) v1(97.94,45.52) v1(97.99,56.11) v1(98.09,43.18) v1(98.25,67.49) v1(98.22,66.7) v1(98.17,65.91) v1(98.32,62.08) v1(98.27,35.71) v1(98.27,34.16) v1(98.37,1.83) v1(98.6,69.9) v1(98.6,64.31) v1(98.68,26.7) v1(98.81,18.62) v1(98.88,59.08) v1(99.03,57.05) v1(99.11,87.3) v1(99.11,68.22) v1(99.06,65.23) v1(99.14,54.56) v1(99.06,50.7) v1(99.16,66.47) v1(99.37,63.32) v1(99.37,60.88) v1(99.44,48.08) v1(99.37,34.29) v1(99.36,23.67) v1(99.54,19.33) v1(99.64,14.55) v1(99.62,7.47) v1(99.62,4.93) v1(99.64,1.83) v1(99.67,46.58) v1(99.75,11.94) v1(99.97,58.04) v1(100.2,0.91) v1(100.28,62.28) v1(100.3,55.96) v1(100.41,50.34) v1(100.43,45.26) v1(100.43,43.21) v1(100.38,40.74) v1(100.48,71.53) v1(100.58,59.66) v1(100.71,66.52) v1(100.71,65.2) v1(100.69,32.26) v1(100.79,64.39) v1(100.76,36.04) v1(100.91,1.83) v1(101.02,57.05) v1(101.22,61.49) v1(101.35,54.58) v1(101.45,63.5) v1(101.47,66.4) v1(101.63,65.2) v1(101.65,64.39) v1(101.7,58.55) v1(101.7,49.48) v1(101.8,31.75) v1(102.11,60.58) v1(102.08,55.91) v1(102.06,47.8) v1(102.18,51.28) v1(102.16,7.47) v1(102.16,4.93) v1(102.18,1.83) v1(102.34,68.25) v1(102.34,62.46) v1(102.26,34.93) v1(102.36,69.85) v1(102.36,35.97) v1(102.57,25.65) v1(102.57,24.41) v1(102.67,71.48) v1(102.67,67.28) v1(102.72,20.22) v1(102.74,0.91) v1(102.84,57.53) v1(102.87,32.36) v1(102.87,22.94) v1(103.15,59.54) v1(103.23,66.47) v1(103.2,65.28) v1(103.25,64.39) v1(103.33,61.57) v1(103.38,69.8) v1(103.38,35.05) v1(103.53,68) v1(103.45,1.83) v1(103.58,30.73) v1(103.66,63.25) v1(103.71,51.08) v1(103.68,31.98) v1(103.81,49.07) v1(104.06,67.08) v1(104.19,58.42) v1(104.27,65.84) v1(104.29,36.04) v1(104.44,69.95) v1(104.37,60.45) v1(104.39,55.88) v1(104.55,62.33) v1(104.65,72.31) v1(104.57,68.07) v1(104.6,34.9) v1(104.7,7.47) v1(104.7,4.93) v1(104.72,1.83) v1(104.9,33.81) v1(105.21,66.52) v1(105.31,76.33) v1(105.33,74.22) v1(105.26,59.54) v1(105.26,57.53) v1(105.28,0.91) v1(105.41,50.52) v1(105.46,71.4) v1(105.49,61.42) v1(105.46,52.15) v1(105.64,70.03) v1(105.69,53.29) v1(105.94,68.38) v1(105.89,49.17) v1(105.99,1.83) v1(106.15,84.53) v1(106.27,66.98) v1(106.35,60.4) v1(106.4,58.5) v1(106.4,56.24) v1(106.71,72.7) v1(106.68,52.04) v1(106.73,51.05) v1(106.81,26.37) v1(106.93,12.93) v1(107.01,52.78) v1(107.21,69.44) v1(107.24,50.39) v1(107.24,7.47) v1(107.24,4.93) v1(107.31,49.17) v1(107.26,1.83) v1(107.44,59.46) v1(107.37,57.58) v1(107.37,51.64) v1(107.37,24.74) v1(107.49,67.92) v1(107.8,73.74) v1(107.82,71.3) v1(107.82,0.91) v1(108.33,76.96) v1(108.36,58.55) v1(108.64,56.16) v1(108.69,72.54) v1(108.71,23.95) v1(108.66,12.09) v1(108.81,51.61) v1(108.86,69.37) v1(108.92,50.34) v1(109.04,75.03) v1(109.02,49.1) v1(109.02,6.05) v1(109.14,68.33) v1(109.17,52.93) v1(109.25,10.74) v1(109.3,85.47) v1(109.32,51.05) v1(109.37,57.66) v1(109.63,52.07) v1(109.55,3.02) v1(109.65,26.77) v1(109.8,59.39) v1(109.88,76.07) v1(109.93,73.46) v1(109.91,25.65) v1(109.98,49.07) v1(110.08,78.51) v1(110.24,23.09) v1(110.36,82.12) v1(110.36,80.85) v1(110.36,7.26) v1(110.36,4.72) v1(110.41,0.99) v1(110.69,69.62) v1(110.82,56.16) v1(110.87,74.96) v1(111.05,77.11) v1(111.05,52.27) v1(111.02,12.29) v1(111.07,87.22) v1(111.07,58.12) v1(111.23,50.39) v1(111.43,59.61) v1(111.43,10.74) v1(111.63,82.12) v1(111.63,80.85) v1(111.61,52.93) v1(111.58,26.85) v1(111.56,2.64) v1(111.66,68.28) v1(111.99,76) v1(111.96,72.59) v1(112.12,28.35) v1(112.19,56.16) v1(112.17,51.36) v1(112.17,25.04) v1(112.34,69.67) v1(112.32,52.45) v1(112.5,61.01) v1(112.57,35.51) v1(112.73,51.77) v1(112.73,30.35) v1(112.83,77.75) v1(112.78,50.39) v1(112.9,70.92) v1(112.88,49.12) v1(112.88,47.7) v1(112.9,7.26) v1(112.9,4.72) v1(113,58.27) v1(112.95,9.53) v1(112.95,0.99) v1(113.16,79.48) v1(113.33,73.53) v1(113.28,67.03) v1(113.44,76.38) v1(113.44,72.09) v1(113.46,11.63) v1(113.61,56.16) v1(113.74,26.57) v1(113.79,45.97) v1(114.05,2.79) v1(114.15,69.42) v1(114.1,68.05) v1(114.12,52.93) v1(114.22,61.65) v1(114.22,59.33) v1(114.2,51.77) v1(114.25,50.29) v1(114.2,47.22) v1(114.17,28.52) v1(114.22,19.23) v1(114.3,48.49) v1(114.4,64.92) v1(114.38,63.65) v1(114.45,77.77) v1(114.58,74.73) v1(114.63,15.85) v1(114.55,13.74) v1(114.73,73.18) v1(114.73,17.48) v1(114.68,5.23) v1(114.83,43) v1(114.83,37.82) v1(115.09,76.4) v1(115.16,35.94) v1(115.42,27.99) v1(115.47,71.98) v1(115.54,39.93) v1(115.49,19.2) v1(115.62,77.72) v1(115.6,56.44) v1(115.7,70.69) v1(115.7,68.2) v1(115.77,66.24) v1(115.82,59.92) v1(115.77,26.14) v1(115.93,63.8) v1(116.03,79.76) v1(115.98,61.67) v1(116.08,58.37) v1(116.13,36.19) v1(116.43,3.86) v1(116.48,69.7) v1(116.61,66.19) v1(116.64,49.91) v1(116.64,48.49) v1(116.66,45.97) v1(116.79,65.28) v1(116.79,62.48) v1(116.94,74.83) v1(117.04,19.25) v1(117.04,17.45) v1(117.14,77.75) v1(117.09,71.88) v1(117.2,60.66) v1(117.37,73.13) v1(117.48,37.14) v1(117.53,25.53) v1(117.48,23.6) v1(117.55,40.82) v1(117.7,69.7) v1(117.72,68.17) v1(117.68,51.87) v1(117.68,50.6) v1(117.91,44.68) v1(117.96,45.95) v1(118.06,47.22) v1(118.11,38.4) v1(118.29,71.53) v1(118.42,74.09) v1(118.36,61.72) v1(118.36,58.32) v1(118.52,76.33) v1(118.57,78.36) v1(118.57,63.6) v1(118.62,57.07) v1(118.72,36.17) v1(119,79.55) v1(118.97,0.94) v1(119.08,65.48) v1(119.28,7.21) v1(119.43,42.39) v1(119.48,59.99) v1(119.53,39.8) v1(119.66,35.66) v1(119.69,12.4) v1(119.91,58.32) v1(119.86,15.34) v1(119.99,31.04) v1(120.14,51.21) v1(120.09,48.46) v1(120.09,37.74) v1(120.24,41.12) v1(120.24,34.65) v1(120.35,79.45) v1(120.27,52.73) v1(120.5,57.05) v1(120.47,39.04) v1(120.55,26.7) v1(120.73,78.66) v1(120.9,20.12) v1(120.98,22.68) v1(121.06,67.01) v1(121.11,65.43) v1(121.16,61.93) v1(121.21,48.51) v1(121.31,51.77) v1(121.26,50.04) v1(121.49,59.99) v1(121.51,58.22) v1(121.51,0.94) v1(121.56,56.54) v1(121.64,52.73) v1(121.56,47.19) v1(121.69,46) v1(121.69,44.73) v1(121.72,43.54) v1(122.02,39.57) v1(122,35.08) v1(121.97,29.21) v1(122.1,20.09) v1(122.25,32.06) v1(122.38,12.9) v1(122.71,53.04) v1(122.73,38) v1(122.81,62.15) v1(122.78,59.28) v1(122.83,56.34) v1(122.78,50.04) v1(122.83,47.19) v1(122.83,43.54) v1(122.76,42.24) v1(122.94,51.92) v1(122.94,48.46) v1(122.89,45.97) v1(122.89,44.65) v1(123.04,67.61) v1(122.99,65.1) v1(123.16,36.63) v1(123.22,20.14) v1(123.34,32.03) v1(123.27,23.9) v1(123.49,41) v1(123.62,35.23) v1(123.62,14.73) v1(123.88,13.39) v1(123.85,0.84) v1(124.05,62.74) v1(124.05,43.31) v1(124.16,67.92) v1(124.16,60.25) v1(124.21,58.01) v1(124.21,55.83) v1(124.18,52.98) v1(124.16,51.82) v1(124.16,50.14) v1(124.16,44.65) v1(124.21,40.23) v1(124.28,78.51) v1(124.26,48.51) v1(124.31,47.19) v1(124.26,45.97) v1(124.31,22.66) v1(124.36,26.98) v1(124.36,20.14) v1(124.82,77.42) v1(124.79,39.27) v1(124.82,16.26) v1(124.87,68.48) v1(124.99,35.97) v1(125.02,33.32) v1(125.07,75.67) v1(125.22,42.88) v1(125.2,37.9) v1(125.32,79.83) v1(125.32,70.69) v1(125.27,69.39) v1(125.32,65.58) v1(125.32,61.72) v1(125.32,58.47) v1(125.32,56.34) v1(125.35,53.09) v1(125.32,48.51) v1(125.32,47.19) v1(125.32,45.97) v1(125.32,44.6) v1(125.4,67.03) v1(125.37,50.14) v1(125.45,13.11) v1(125.63,29.77) v1(125.76,14.66) v1(125.88,17.63) v1(125.98,31.95) v1(126.01,5.54) v1(126.14,69.14) v1(126.16,72.49) v1(126.21,44.04) v1(126.29,70.23) v1(126.34,49.94) v1(126.34,48.51) v1(126.34,37.41) v1(126.39,82.4) v1(126.42,67.31) v1(126.39,65.28) v1(126.39,62.53) v1(126.39,57.91) v1(126.39,55.73) v1(126.36,53.14) v1(126.42,47.19) v1(126.36,42.52) v1(126.36,39.65) v1(126.39,0.84) v1(126.47,45.87) v1(126.59,78.89) v1(126.64,28.91) v1(126.87,75.06) v1(126.95,27.23) v1(127,74.04) v1(126.97,43.23) v1(127.1,84.61) v1(127.23,72.62) v1(127.23,35.48) v1(127.25,45.39) v1(127.28,39.04) v1(127.43,76.73) v1(127.38,66.52) v1(127.38,65.3) v1(127.51,67.49) v1(127.51,48.56) v1(127.53,40.41) v1(127.56,58.01) v1(127.56,52.93) v1(127.61,42.34) v1(127.66,59.99) v1(127.66,56.64) v1(127.66,55.83) v1(127.69,51.89) v1(127.66,41.17) v1(127.79,81.1) v1(127.79,47.22) v1(127.89,74.96) v1(127.89,69.75) v1(127.94,64.62) v1(127.91,50.39) v1(127.94,44.73) v1(127.91,32) v1(127.94,26.09) v1(127.97,68.17) v1(128.14,34.06) v1(128.27,36.58) v1(128.3,23.27) v1(128.42,25.07) v1(128.65,5.79) v1(128.88,31.14) v1(128.96,29.11) v1(129.18,76.66) v1(129.29,27.48) v1(129.39,62.89) v1(129.49,73.05) v1(129.46,69.57) v1(129.49,39.83) v1(129.74,55.78) v1(129.79,89.33) v1(129.79,60.02) v1(129.82,52.73) v1(129.82,47.17) v1(129.79,35.76) v1(129.85,33.33) v1(129.84,24.89) v1(129.87,72.21) v1(129.92,52.04) v1(129.87,44.58) v1(129.92,40.72) v1(129.95,38) v1(130.05,67.23) v1(130.05,66.09) v1(130.05,65.05) v1(130,58.17) v1(130,50.55) v1(130.05,48.62) v1(130.07,62.18) v1(130.23,75.69) v1(130.23,70) v1(130.23,63.93) v1(130.25,74.02) v1(130.25,68.1) v1(130.53,28.42) v1(130.48,3.86) v1(130.71,36.73) v1(130.68,30.89) v1(130.71,5.16) v1(130.81,40.13) v1(131.04,38.99) v1(131.24,26.34) v1(131.32,73.81) v1(131.45,11.23) v1(131.52,35.61) v1(131.62,71.35) v1(131.62,62.97) v1(131.65,60.55) v1(131.62,48.62) v1(131.62,33.93) v1(131.72,76.71) v1(131.67,69.34) v1(131.72,53.44) v1(131.72,52.22) v1(131.72,44.63) v1(131.67,28.5) v1(131.8,67.36) v1(131.75,65.3) v1(131.83,50.24) v1(131.78,12.14) v1(131.85,72.24) v1(131.9,58.5) v1(131.93,55.93) v1(131.88,24.77) v1(131.88,22.2) v1(131.93,19.66) v1(132.03,75.64) v1(132.13,77.83) v1(132.05,47.24) v1(132.13,17.78) v1(132.18,32.36) v1(132.21,6.35) v1(132.18,3.38) v1(132.33,29.67) v1(132.28,1.19) v1(132.38,38.76) v1(132.49,62.1) v1(132.54,59.44) v1(132.61,45.03) v1(132.56,40.97) v1(132.66,70.41) v1(132.69,49.68) v1(132.66,47.8) v1(132.74,30.94) v1(132.69,27.64) v1(132.66,13.03) v1(132.89,20.73) v1(133.05,68.43) v1(133.02,67.34) v1(132.99,65.89) v1(132.99,64.57) v1(133.1,51.36) v1(133.15,35.41) v1(133.1,23.42) v1(133.25,18.95) v1(133.27,61.32) v1(133.3,50.39) v1(133.27,45.85) v1(133.3,26.16) v1(133.4,71.17) v1(133.35,48.54) v1(133.4,41.5) v1(133.53,42.55) v1(133.45,37.59) v1(133.55,53.39) v1(133.68,63.4) v1(133.71,44.81) v1(133.83,57.18) v1(133.81,6.38) v1(133.76,2.24) v1(133.91,76.3) v1(133.91,73.91) v1(133.88,55.7) v1(133.86,39.83) v1(133.88,33.93) v1(133.91,21.74) v1(133.93,12.19) v1(133.96,72.21) v1(133.96,50.95) v1(133.96,32.11) v1(134.09,60.48) v1(134.06,58.17) v1(134.11,49.33) v1(134.16,77.72) v1(134.24,43.21) v1(134.16,24.28) v1(134.19,4.67) v1(134.39,89.41) v1(134.37,29.82) v1(134.37,27.38) v1(134.37,20.04) v1(134.49,46.1) v1(134.52,36.78) v1(134.59,62.46) v1(134.59,45.16) v1(134.57,38.96) v1(134.67,70.13) v1(134.7,67.44) v1(134.67,65.13) v1(134.77,9.98) v1(134.85,1.19) v1(134.87,59.64) v1(134.92,56.52) v1(134.92,30.94) v1(134.92,17.78) v1(134.95,87.78) v1(134.95,86.51) v1(135.1,15.85) v1(135.05,7.54) v1(135.15,25.22) v1(135.26,46.96) v1(135.26,43.59) v1(135.43,52.93) v1(135.43,18.9) v1(135.48,70.89) v1(135.51,45.95) v1(135.53,35.86) v1(135.59,58.88) v1(135.64,48.64) v1(135.64,23.57) v1(135.74,77.72) v1(135.74,76.3) v1(135.69,72.21) v1(135.69,33.68) v1(135.79,73.94) v1(135.79,61.29) v1(135.79,56.24) v1(135.86,68.07) v1(135.86,66.24) v1(135.86,64.54) v1(135.89,51.46) v1(135.92,44.25) v1(135.94,29.87) v1(135.86,27.2) v1(135.89,21.44) v1(135.86,15.98) v1(135.97,50.24) v1(136.14,28.3) v1(136.09,26.26) v1(136.09,12.75) v1(136.22,87.78) v1(136.22,86.51) v1(136.25,47.78) v1(136.25,38.46) v1(136.25,7.54) v1(136.35,58.17) v1(136.35,46.66) v1(136.3,39.83) v1(136.35,14.53) v1(136.37,62.99) v1(136.5,53.39) v1(136.53,11.86) v1(136.63,45.03) v1(136.6,32.26) v1(136.83,1.04) v1(136.91,24.77) v1(137.03,48.95) v1(136.96,19.86) v1(137.06,59.94) v1(137.11,22.81) v1(137.21,77.77) v1(137.24,68.35) v1(137.24,55.02) v1(137.21,35.36) v1(137.21,6.02) v1(137.26,66.8) v1(137.34,64.39) v1(137.31,51.51) v1(137.31,40.94) v1(137.26,30.43) v1(137.36,70.13) v1(137.36,45.67) v1(137.36,16.03) v1(137.52,76.2) v1(137.46,37.79) v1(137.52,34.19) v1(137.52,11.91) v1(137.62,73.91) v1(137.62,72.19) v1(137.57,61.82) v1(137.57,42.47) v1(137.59,27.86) v1(137.57,26.03) v1(137.57,8.05) v1(137.72,52.7) v1(137.77,39.12) v1(137.87,56.72) v1(137.9,48.01) v1(137.92,21.39) v1(138.02,50.24) v1(138.07,45.82) v1(138.07,26.97) v1(138.07,18.57) v1(138.23,44.4) v1(138.23,36.27) v1(138.18,29.36) v1(138.28,38.35) v1(138.28,32.41) v1(138.38,51.56) v1(138.43,42.98) v1(138.38,23.93) v1(138.48,53.87) v1(138.51,6.88) v1(138.63,77.88) v1(138.58,41.3) v1(138.73,0.86) v1(138.84,66.37) v1(138.84,62.74) v1(138.76,55.73) v1(138.76,47.12) v1(138.79,39.62) v1(138.86,13.54) v1(138.99,60.4) v1(139.04,34.24) v1(139.06,21.77) v1(139.19,87.83) v1(139.19,86.56) v1(139.19,72.19) v1(139.24,67.97) v1(139.22,24.79) v1(139.29,75.84) v1(139.34,74.37) v1(139.27,70.18) v1(139.27,35.33) v1(139.32,1.7) v1(139.45,44.25) v1(139.5,30.94) v1(139.6,54.81) v1(139.65,27.23) v1(139.65,23.16) v1(139.69,50.24) v1(139.8,52.58) v1(139.75,42.98) v1(139.93,26.42) v1(140.13,36.47) v1(140.08,35.69) v1(140.06,12.12) v1(140.13,10.41) v1(140.23,59.08) v1(140.23,56.74) v1(140.18,34.11) v1(140.23,20.35) v1(140.31,39.17) v1(140.34,25.2) v1(140.31,7.77) v1(140.41,38.25) v1(140.46,87.83) v1(140.46,86.56) v1(140.49,2.49) v1(140.56,68.28) v1(140.61,53.9) v1(140.69,23.62) v1(140.79,73.86) v1(140.87,51.51) v1(140.97,48.95) v1(141.02,8.86) v1(141.2,58.06) v1(141.2,27.15) v1(141.17,5.92) v1(141.22,4.14) v1(141.3,1.78) v1(141.43,89.41) v1(141.4,75.74) v1(141.4,10.41) v1(141.5,69.85) v1(141.45,25.1) v1(141.66,0.89) v1(141.88,52.83) v1(141.94,48.97) v1(141.94,21.49) v1(141.99,55.07) v1(142.04,26.36) v1(141.96,23.8) v1(142.06,27.28) v1(142.14,8.05) v1(142.14,5.94) v1(142.24,59.64) v1(142.24,50.24) v1(142.19,4.17) v1(142.21,2.59) v1(142.39,56.79) v1(142.39,12.17) v1(142.54,46.91) v1(142.47,45.67) v1(142.52,44.3) v1(142.47,34.54) v1(142.49,33.43) v1(142.54,32.26) v1(142.52,31.22) v1(142.52,29.49) v1(142.6,75.77) v1(142.6,39.93) v1(142.62,35.61) v1(142.75,42.88) v1(142.75,42.11) v1(142.72,40.64) v1(142.7,39.12) v1(142.67,38.38) v1(142.7,36.96) v1(142.72,10.36) v1(142.85,77.57) v1(142.8,47.6) v1(142.8,43.61) v1(142.82,41.33) v1(142.77,37.64) v1(142.93,74.09) v1(142.93,46.13) v1(142.93,36.3) v1(143,34.98) v1(142.98,32.84) v1(142.98,31.7) v1(142.98,30.61) v1(142.95,29.97) v1(143.05,45.24) v1(143.21,8.15) v1(143.23,6.1) v1(143.31,23.9) v1(143.28,4.32) v1(143.36,76.45) v1(143.36,59.72) v1(143.51,55.63) v1(143.46,50.24) v1(143.61,57.91) v1(143.56,51.51) v1(143.66,54.15) v1(143.74,27.41) v1(143.71,12.12) v1(143.74,10.49) v1(143.71,1.07) v1(143.76,26.21) v1(143.79,24.99) v1(143.96,48.95) v1(144.04,8.92) v1(144.15,75.29) v1(144.2,3.3) v1(144.35,89.26) v1(144.45,60.88) v1(144.53,22.05) v1(144.58,52.83) v1(144.68,55.52) v1(144.69,50.21) v1(144.81,23.9) v1(144.86,58.67) v1(144.86,27.51) v1(144.98,12.6) v1(145.11,41.66) v1(145.14,40.56) v1(145.14,34.82) v1(145.11,10.62) v1(145.21,68.3) v1(145.24,39.32) v1(145.21,36.93) v1(145.16,35.71) v1(145.34,56.79) v1(145.29,38.15) v1(145.34,26.24) v1(145.34,2.01) v1(145.49,66.75) v1(145.8,70.05) v1(145.8,47.45) v1(145.85,43.69) v1(145.82,35.97) v1(145.85,24.97) v1(145.9,28.75) v1(145.97,77.11) v1(146,59.54) v1(146,48.97) v1(146.08,65.99) v1(146.1,63.04) v1(146.05,57.91) v1(146.1,36.86) v1(146.15,61.44) v1(146.3,55.52) v1(146.3,51.51) v1(146.3,50.24) v1(146.25,30.63) v1(146.3,27.23) v1(146.25,19.86) v1(146.41,74.98) v1(146.41,22.23) v1(146.46,54.15) v1(146.51,38.48) v1(146.46,17.35) v1(146.58,41.38) v1(146.63,36.52) v1(146.63,33.35) v1(146.56,13.64) v1(146.66,32.05) v1(146.76,56.79) v1(146.79,45.59) v1(146.81,43.64) v1(146.86,25.98) v1(146.96,69.14) v1(147.04,0.86) v1(147.07,89.41) v1(147.09,39.67) v1(147.17,28.8) v1(147.22,11.71) v1(147.27,34.67) v1(147.32,30.2) v1(147.37,52.83) v1(147.42,36.02) v1(147.57,49.58) v1(147.57,44.15) v1(147.57,43.13) v1(147.6,23.75) v1(147.7,37.26) v1(147.68,33.4) v1(147.65,13.23) v1(147.83,79.4) v1(147.83,78.13) v1(147.78,66.85) v1(147.78,59.23) v1(147.8,51.03) v1(147.75,38.46) v1(148.01,64.62) v1(148.03,28.88) v1(148.06,73.3) v1(148.11,62.97) v1(148.11,34.72) v1(148.08,30.68) v1(148.21,27.28) v1(148.34,60.91) v1(148.26,32.05) v1(148.44,71.2) v1(148.41,57.94) v1(148.44,55.52) v1(148.49,21.89) v1(148.59,53.72) v1(148.59,0.84) v1(148.74,41.22) v1(148.69,11.53) v1(148.77,50.06) v1(148.77,25.83) v1(148.89,39.6) v1(148.97,51.64) v1(149.1,79.4) v1(149.1,78.13) v1(149.1,72.16) v1(149.15,67.18) v1(149.07,47.52) v1(149.07,45.77) v1(149.07,44.3) v1(149.07,42.57) v1(149.3,69.27) v1(149.33,37.31) v1(149.33,36.32) v1(149.3,35.37) v1(149.43,64.14) v1(149.38,56.87) v1(149.48,28.78) v1(149.45,24.46) v1(149.56,62.33) v1(149.56,33.17) v1(149.58,31.27) v1(149.58,12.19) v1(149.73,76.07) v1(149.73,74.8) v1(149.81,60.17) v1(149.81,54.33) v1(149.89,50.6) v1(150.01,58.09) v1(150.06,52.25) v1(150.06,30.28) v1(150.22,37.52) v1(150.29,48.46) v1(150.29,45.67) v1(150.32,41.4) v1(150.34,39.47) v1(150.52,20.7) v1(150.57,55.65) v1(150.65,11.43) v1(150.72,79.6) v1(150.72,27.2) v1(150.83,28.8) v1(150.93,22.99) v1(151,76.07) v1(151,74.8) v1(151.03,32.72) v1(151.13,52.96) v1(151.08,31.29) v1(151.23,51.08) v1(151.18,1.12) v1(151.56,48.31) v1(151.61,45.67) v1(151.61,42.77) v1(151.56,38.35) v1(151.59,36.17) v1(151.69,12.22) v1(151.84,61.09) v1(152.07,80.95) v1(152.15,78.13) v1(152.25,54.1) v1(152.35,21.82) v1(152.43,51.66) v1(152.73,32.64) v1(152.83,46.46) v1(152.83,39.37) v1(152.81,30.81) v1(152.78,29.41) v1(152.86,48.87) v1(152.86,43.23) v1(152.86,36.65) v1(152.86,34.82) v1(153.11,20.32) v1(153.29,12.62) v1(153.31,10.52) v1(153.34,2.72) v1(153.44,53.01) v1(153.52,77.65) v1(153.64,25.6) v1(153.64,23.27) v1(153.72,80.39) v1(153.75,27.36) v1(153.82,63.7) v1(153.85,61.29) v1(153.95,67.56) v1(153.87,58.65) v1(153.92,56.24) v1(153.92,54.66) v1(154,75.21) v1(154.03,73.36) v1(154.03,69.29) v1(154.05,71.35) v1(154.13,48.01) v1(154.13,43.74) v1(154.13,39.19) v1(154.13,7.75) v1(154.08,4.14) v1(154.18,83.57) v1(154.18,52.12) v1(154.18,51.05) v1(154.18,50.09) v1(154.18,48.92) v1(154.18,46.86) v1(154.15,45.8) v1(154.15,44.73) v1(154.18,42.55) v1(154.15,41.55) v1(154.15,40.34) v1(154.15,37.95) v1(154.18,36.91) v1(154.18,35.79) v1(154.15,34.82) v1(154.18,33.81) v1(154.15,32.87) v1(154.15,31.98) v1(154.15,31.06) v1(154.15,30.02) v1(154.15,29.06) v1(154.18,9.42) v1(154.15,5.87)
